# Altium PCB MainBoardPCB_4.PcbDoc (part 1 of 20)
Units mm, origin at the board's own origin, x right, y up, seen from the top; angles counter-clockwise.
Board outline 333.63 x 349.38 mm, 16 copper layers (L1, L2 (GND), L3 (Sign), L4 (GND), L5 (Sign), L6 (PWR/GND), L7(PWR/GND), L8 (Plane_GND), L9 (PWR/GND), L10 (PWR/GND), L11 (PWR/GND), L12 (Sign), L13 (GND), L14 (Sign), L15 (GND), L16), stack 2.502 mm thick; 2205 components, 1648 nets, 8314 pads, 3172 vias.
Unrouted connection lines stored in the file: 5141.
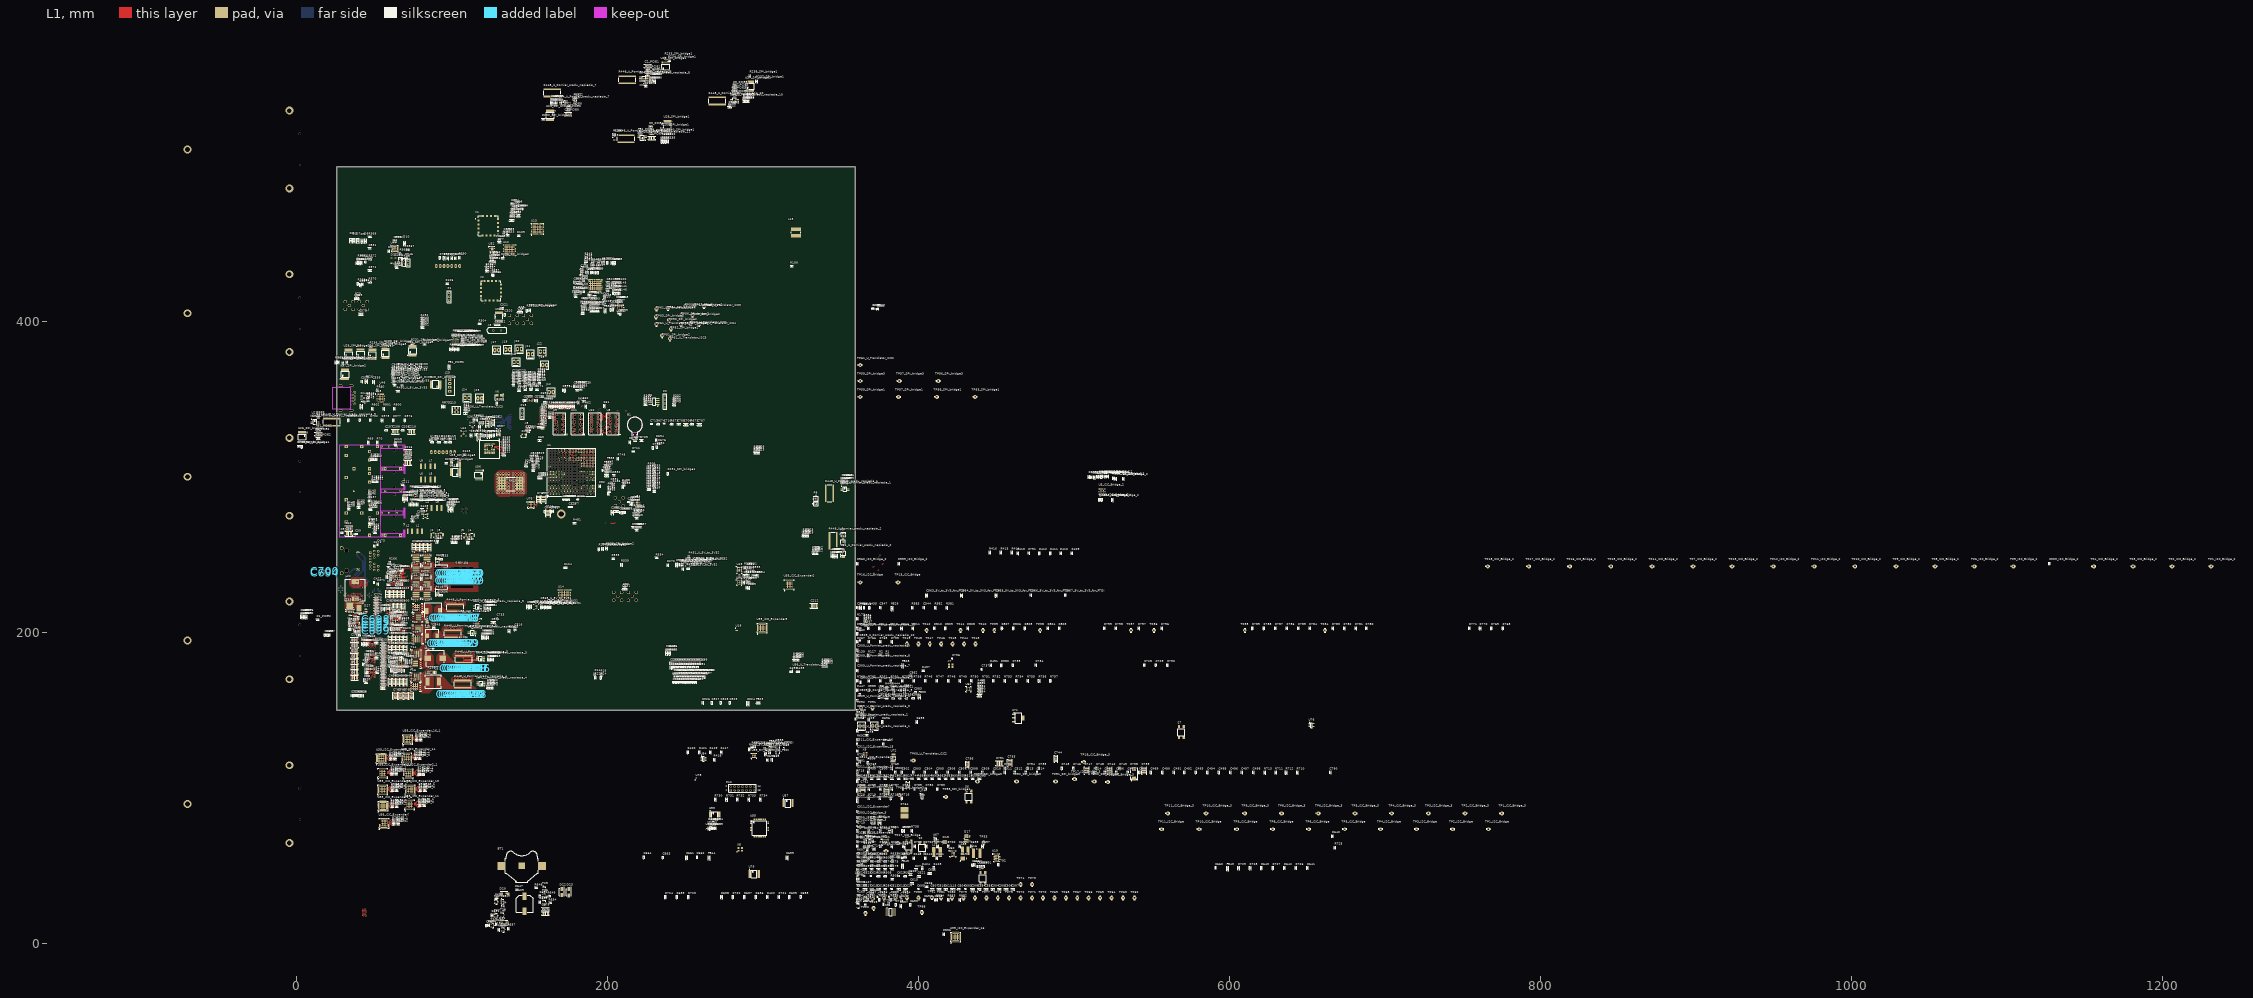
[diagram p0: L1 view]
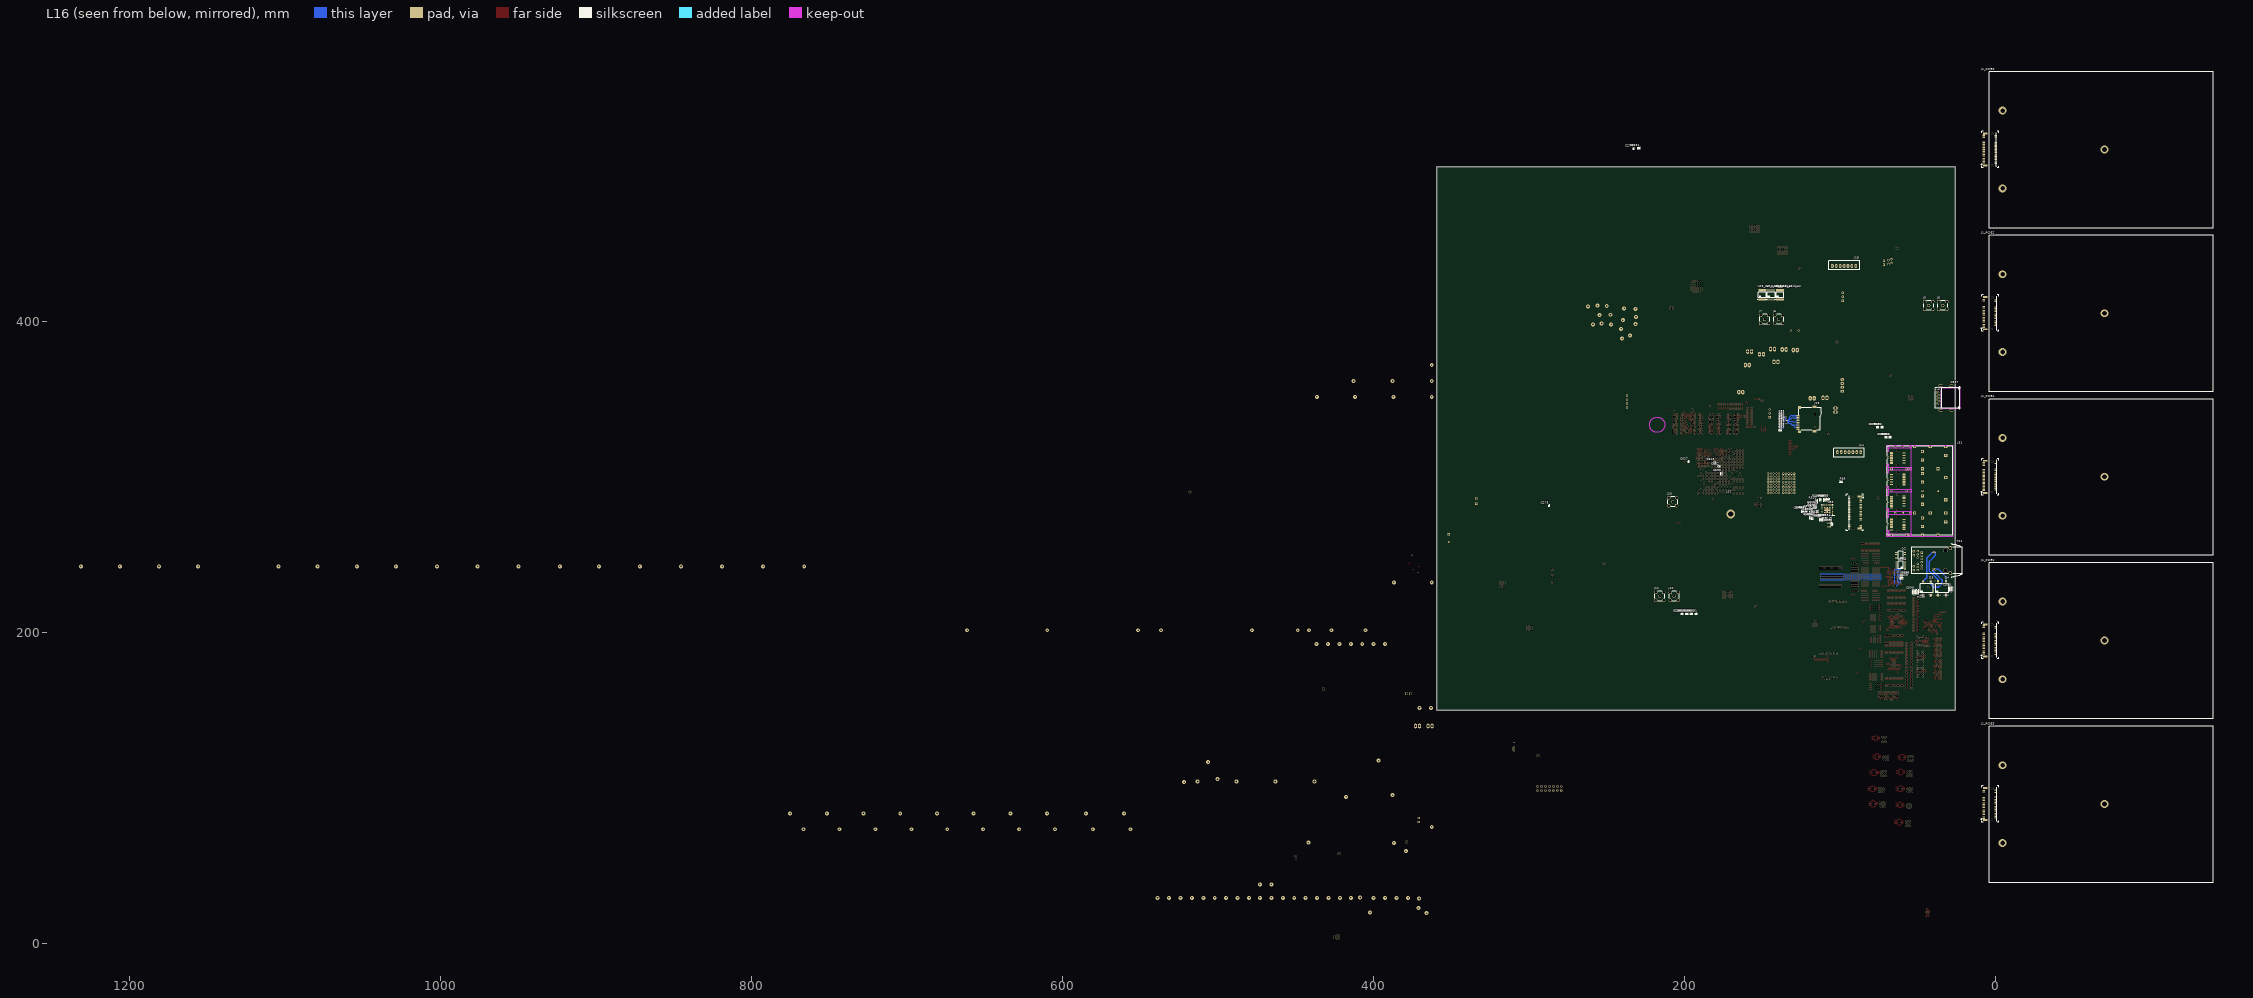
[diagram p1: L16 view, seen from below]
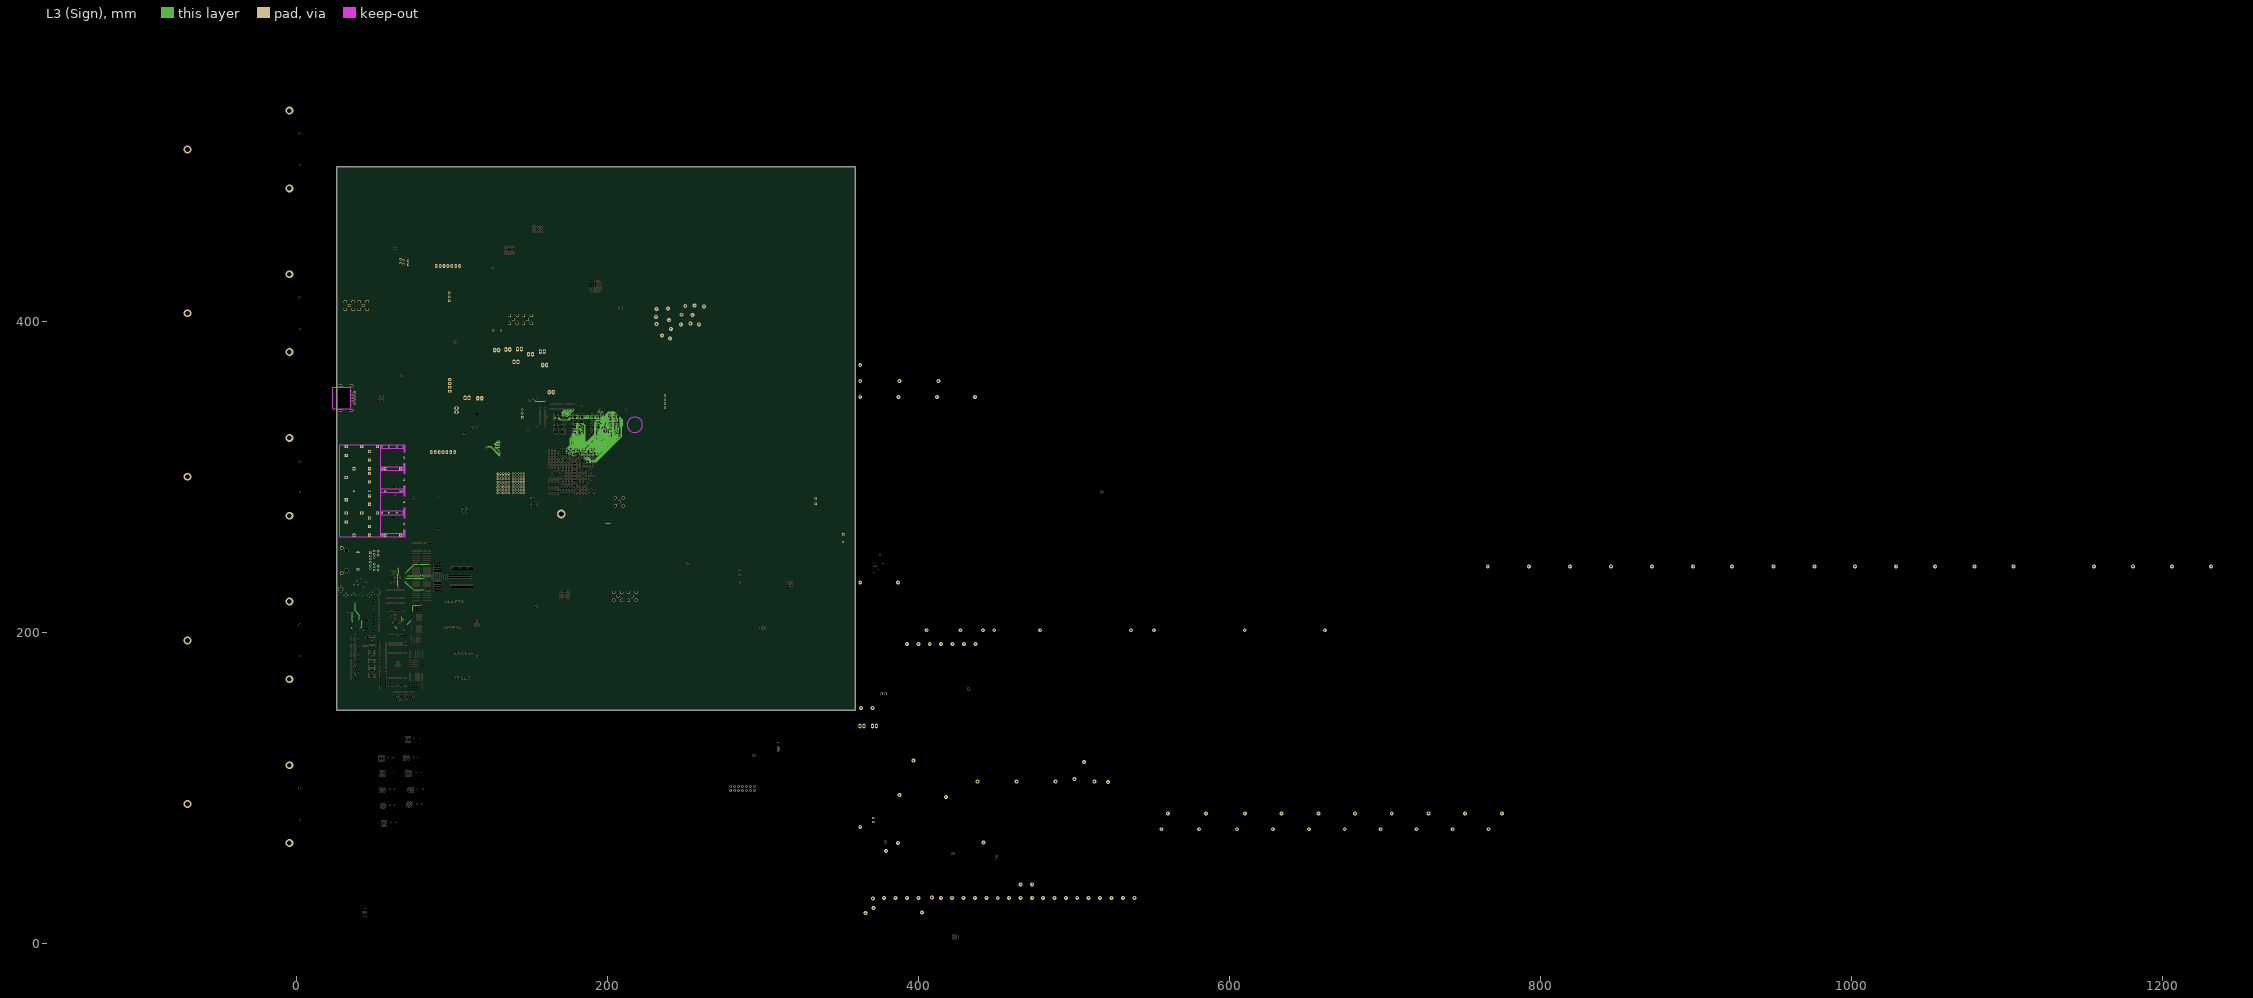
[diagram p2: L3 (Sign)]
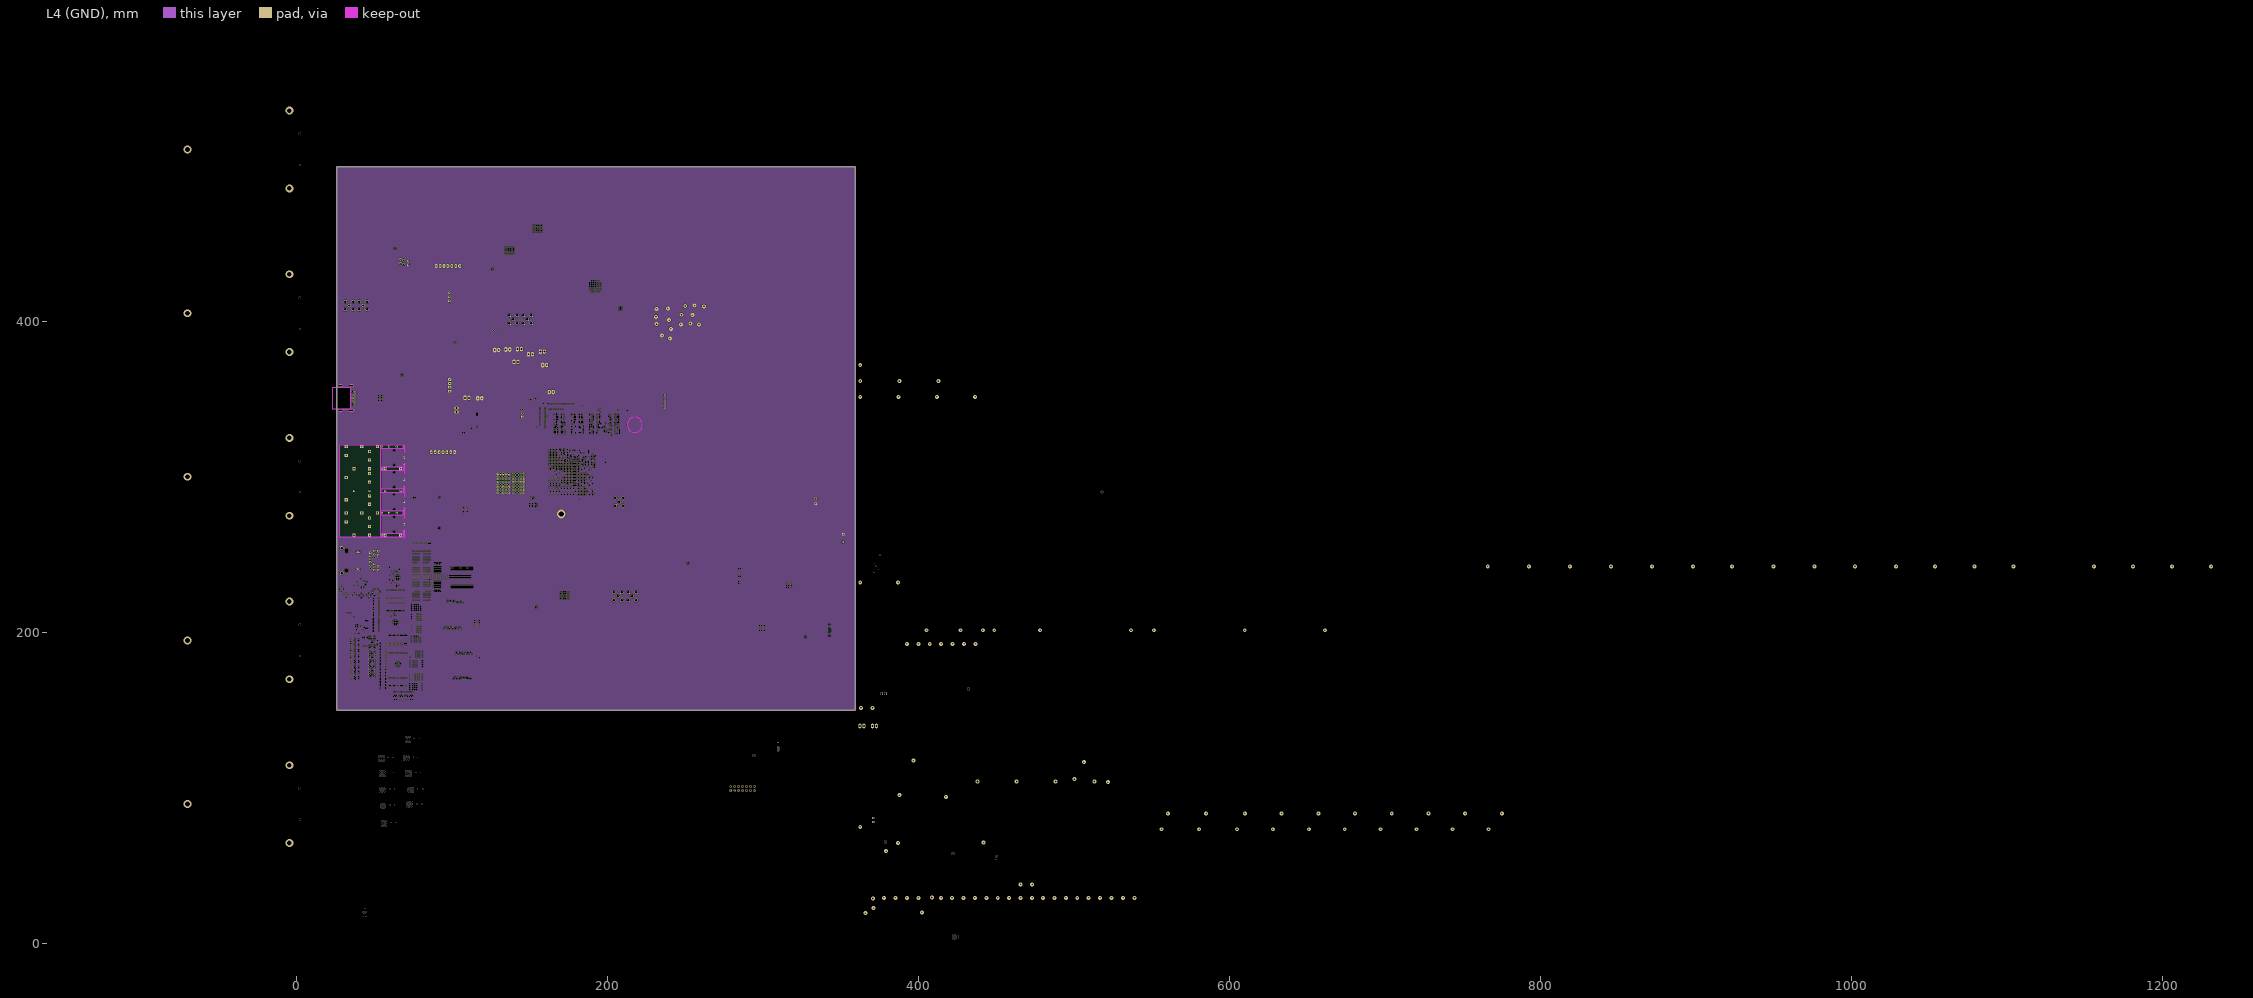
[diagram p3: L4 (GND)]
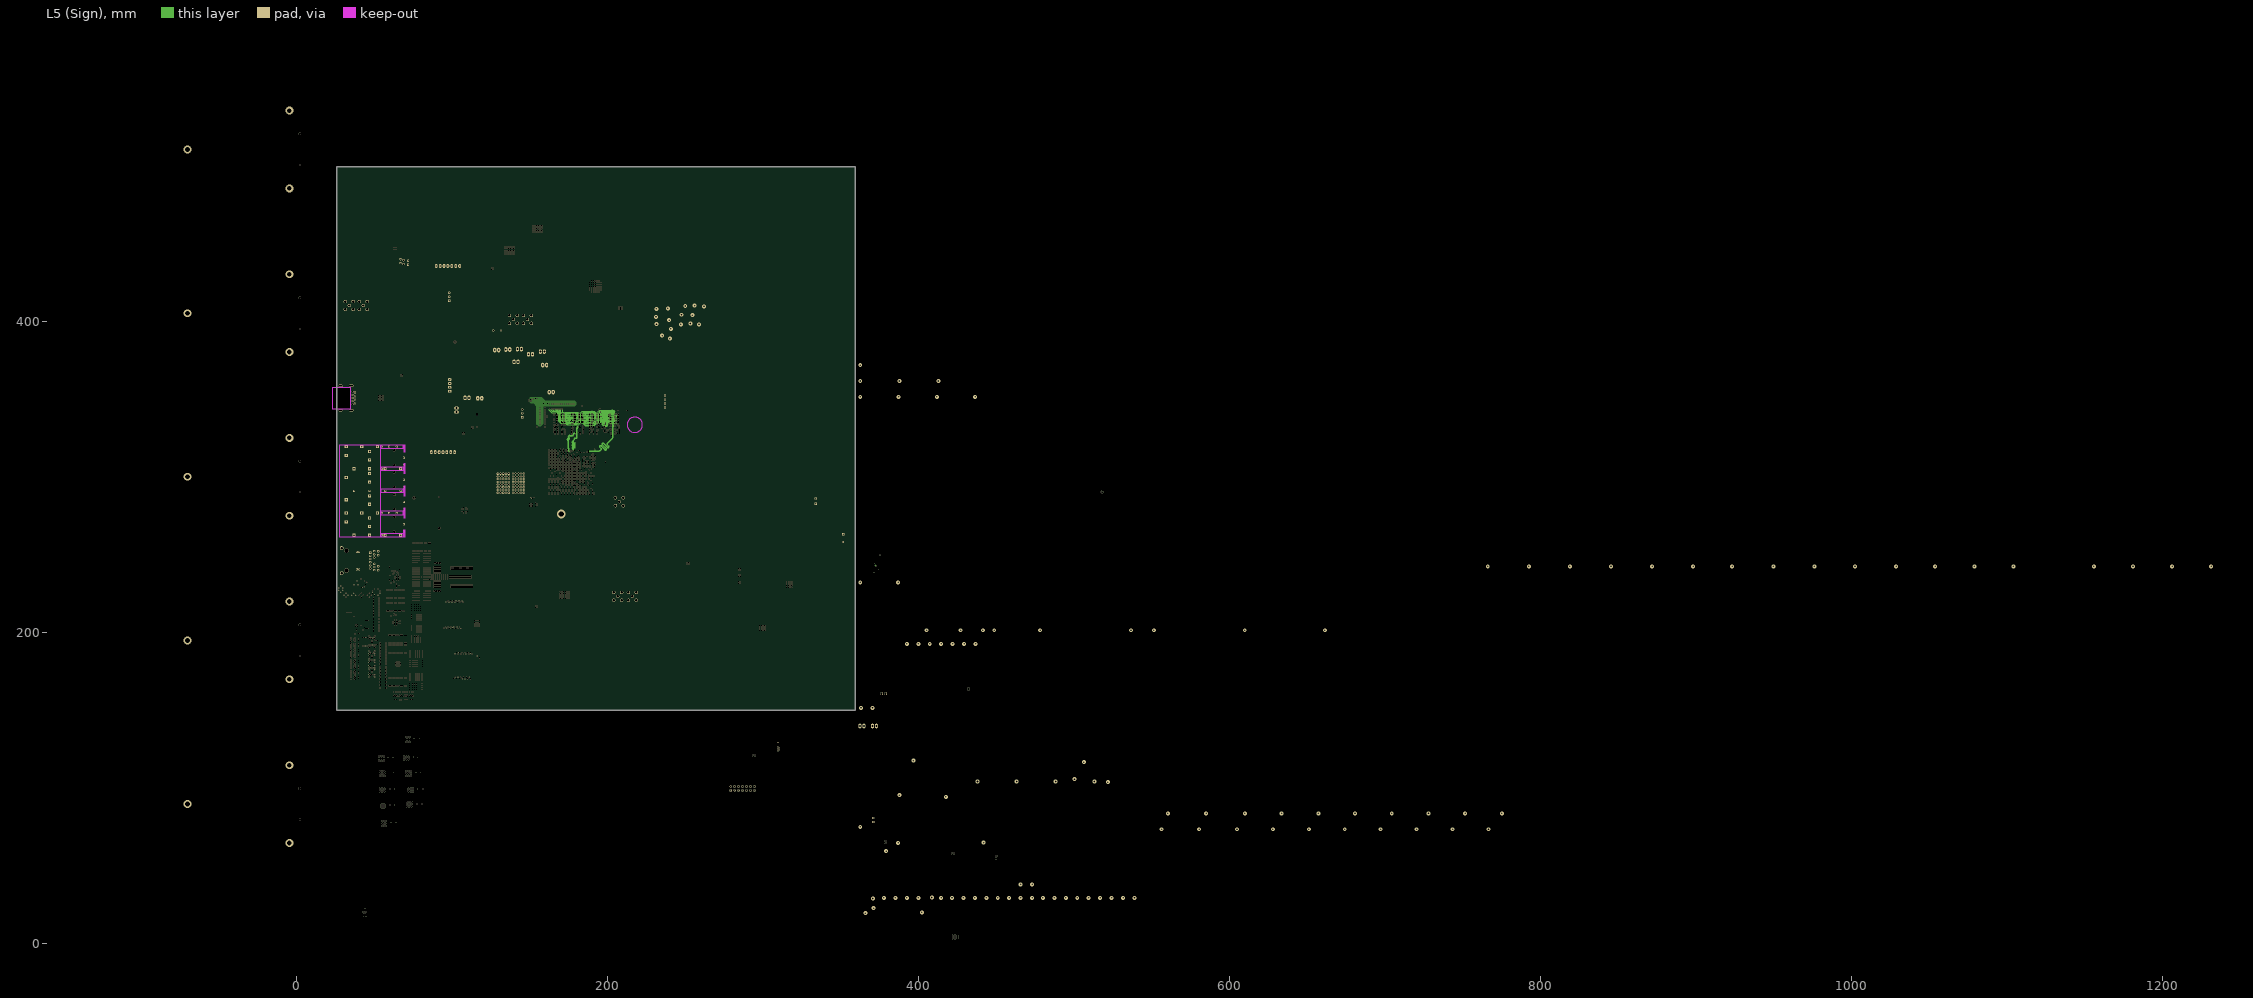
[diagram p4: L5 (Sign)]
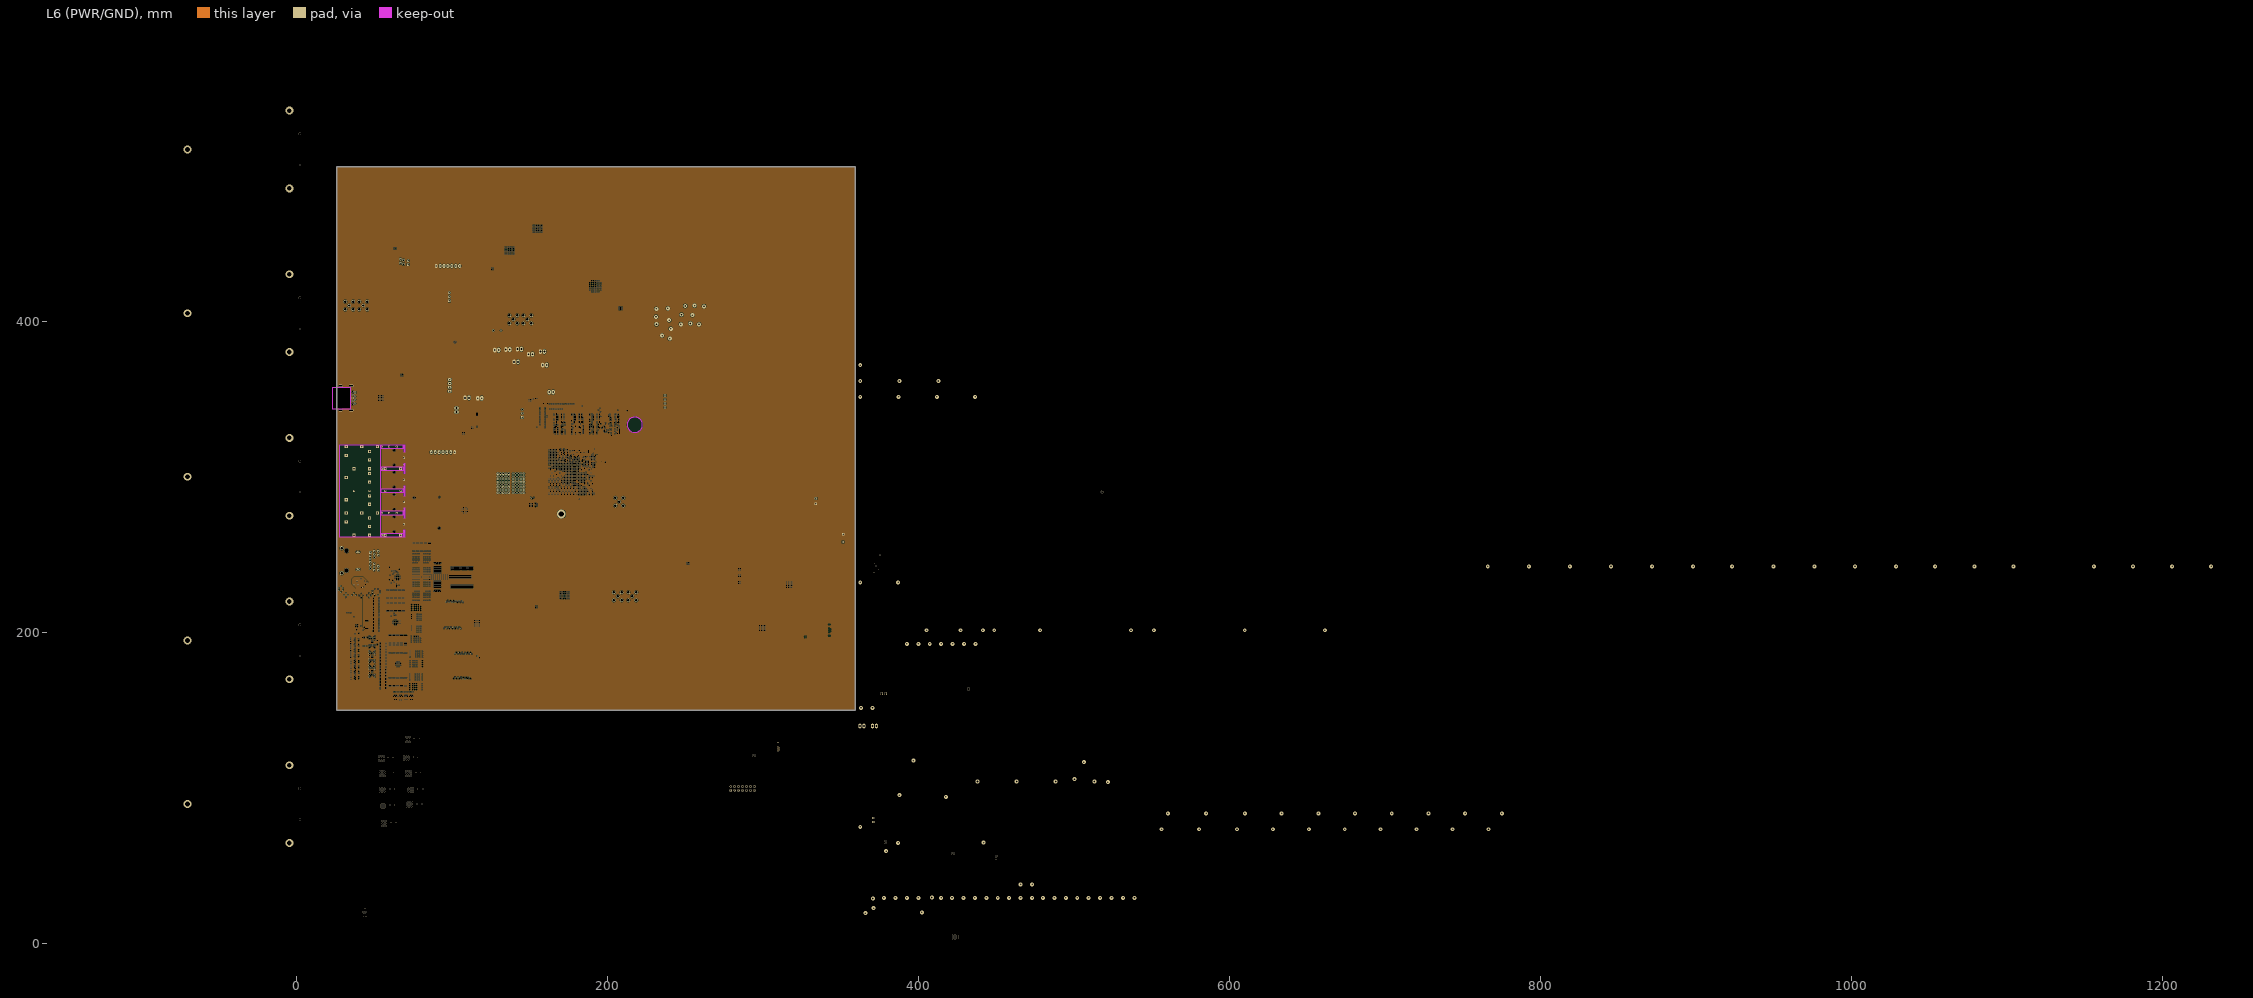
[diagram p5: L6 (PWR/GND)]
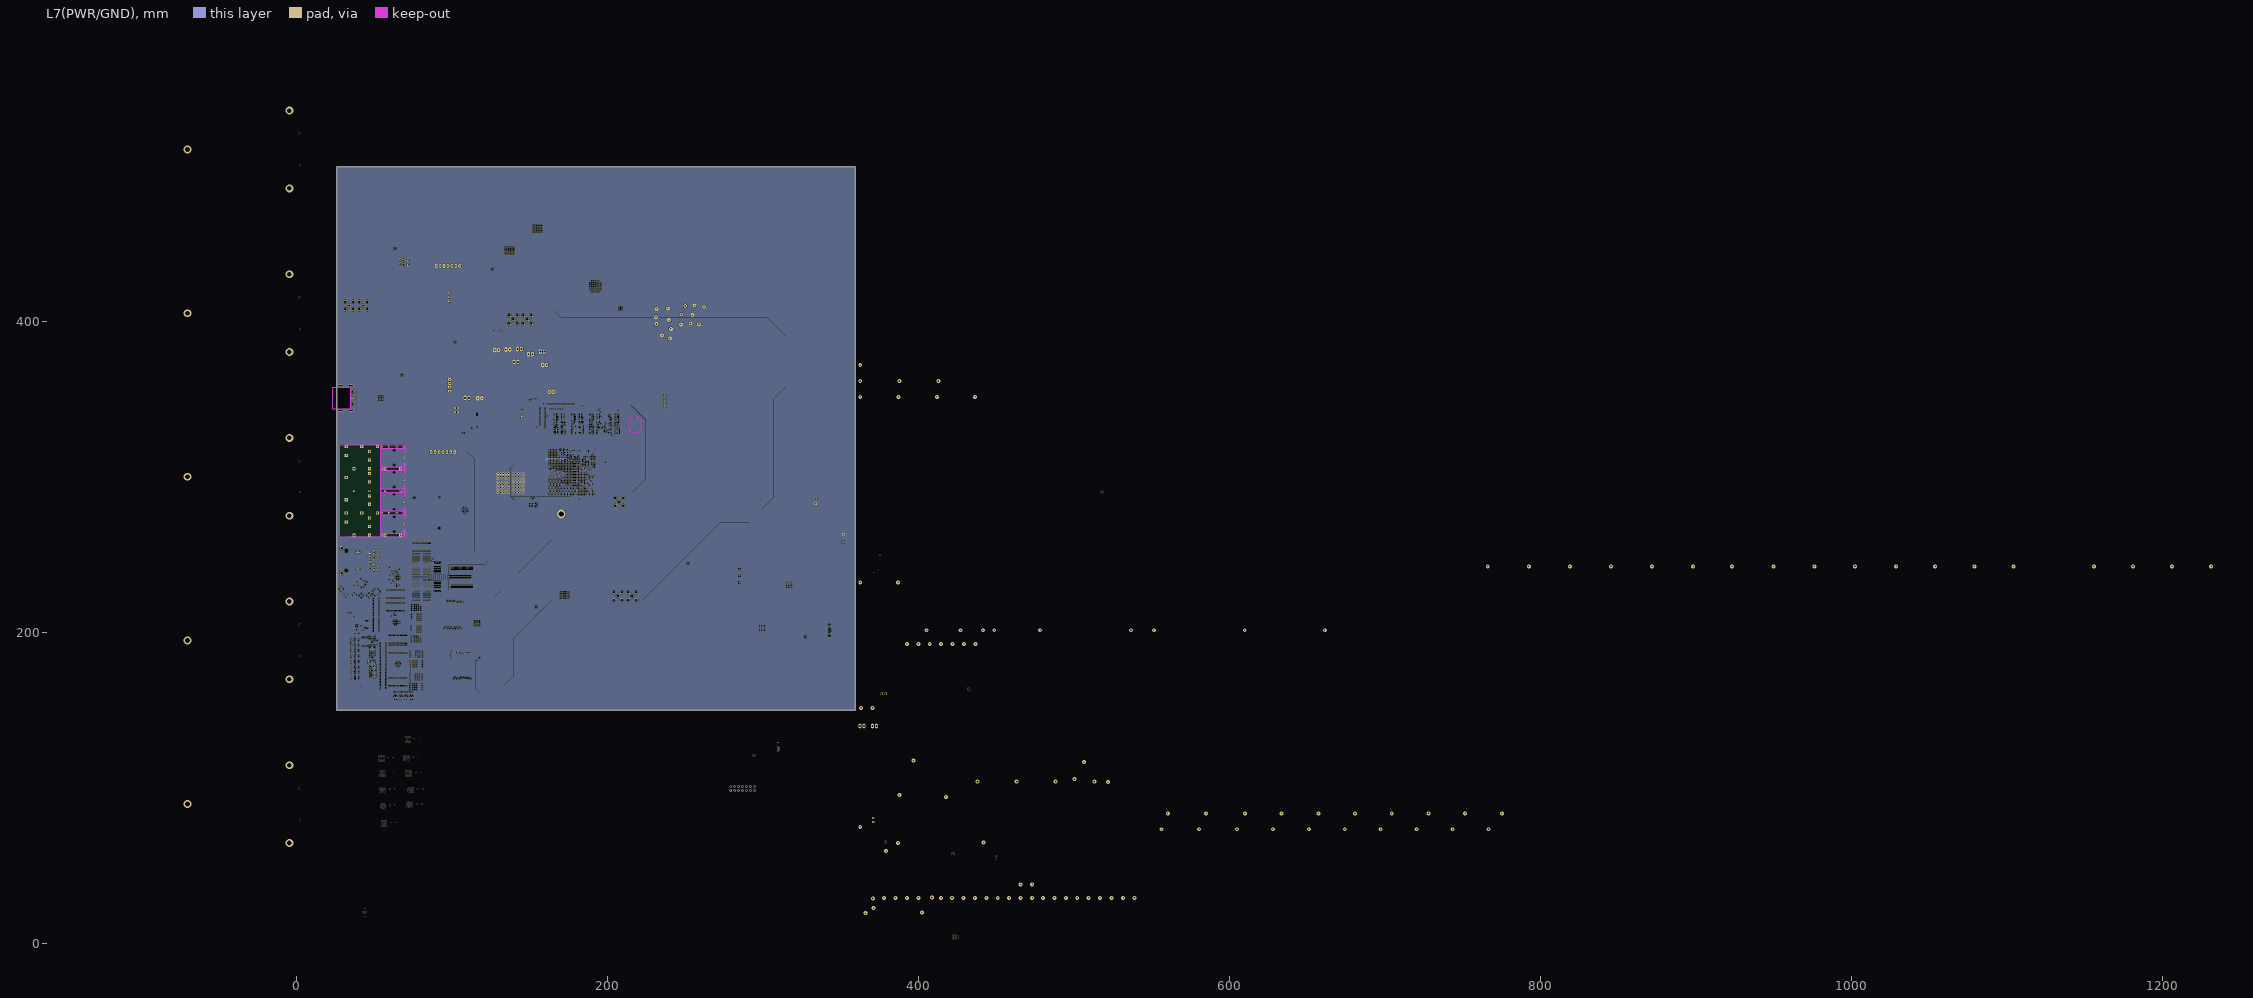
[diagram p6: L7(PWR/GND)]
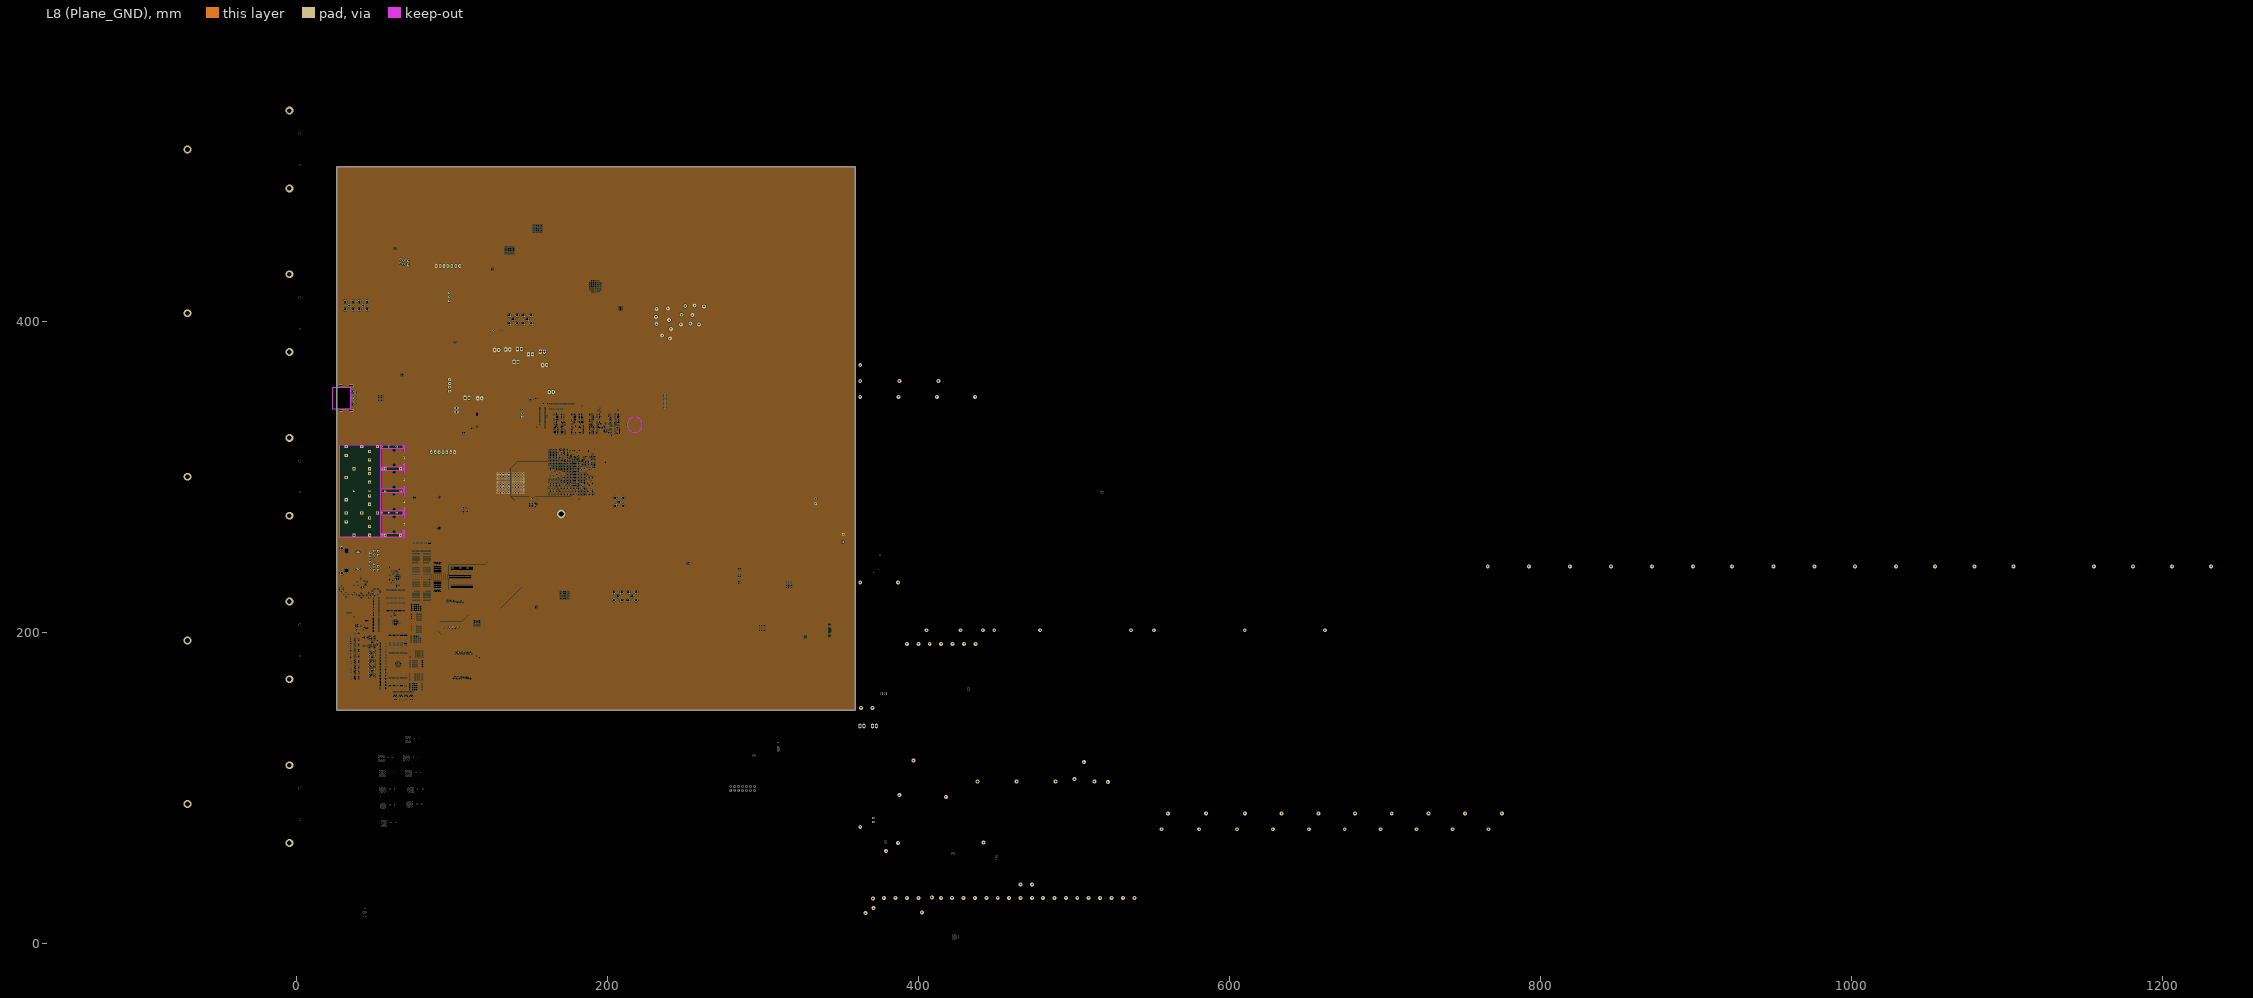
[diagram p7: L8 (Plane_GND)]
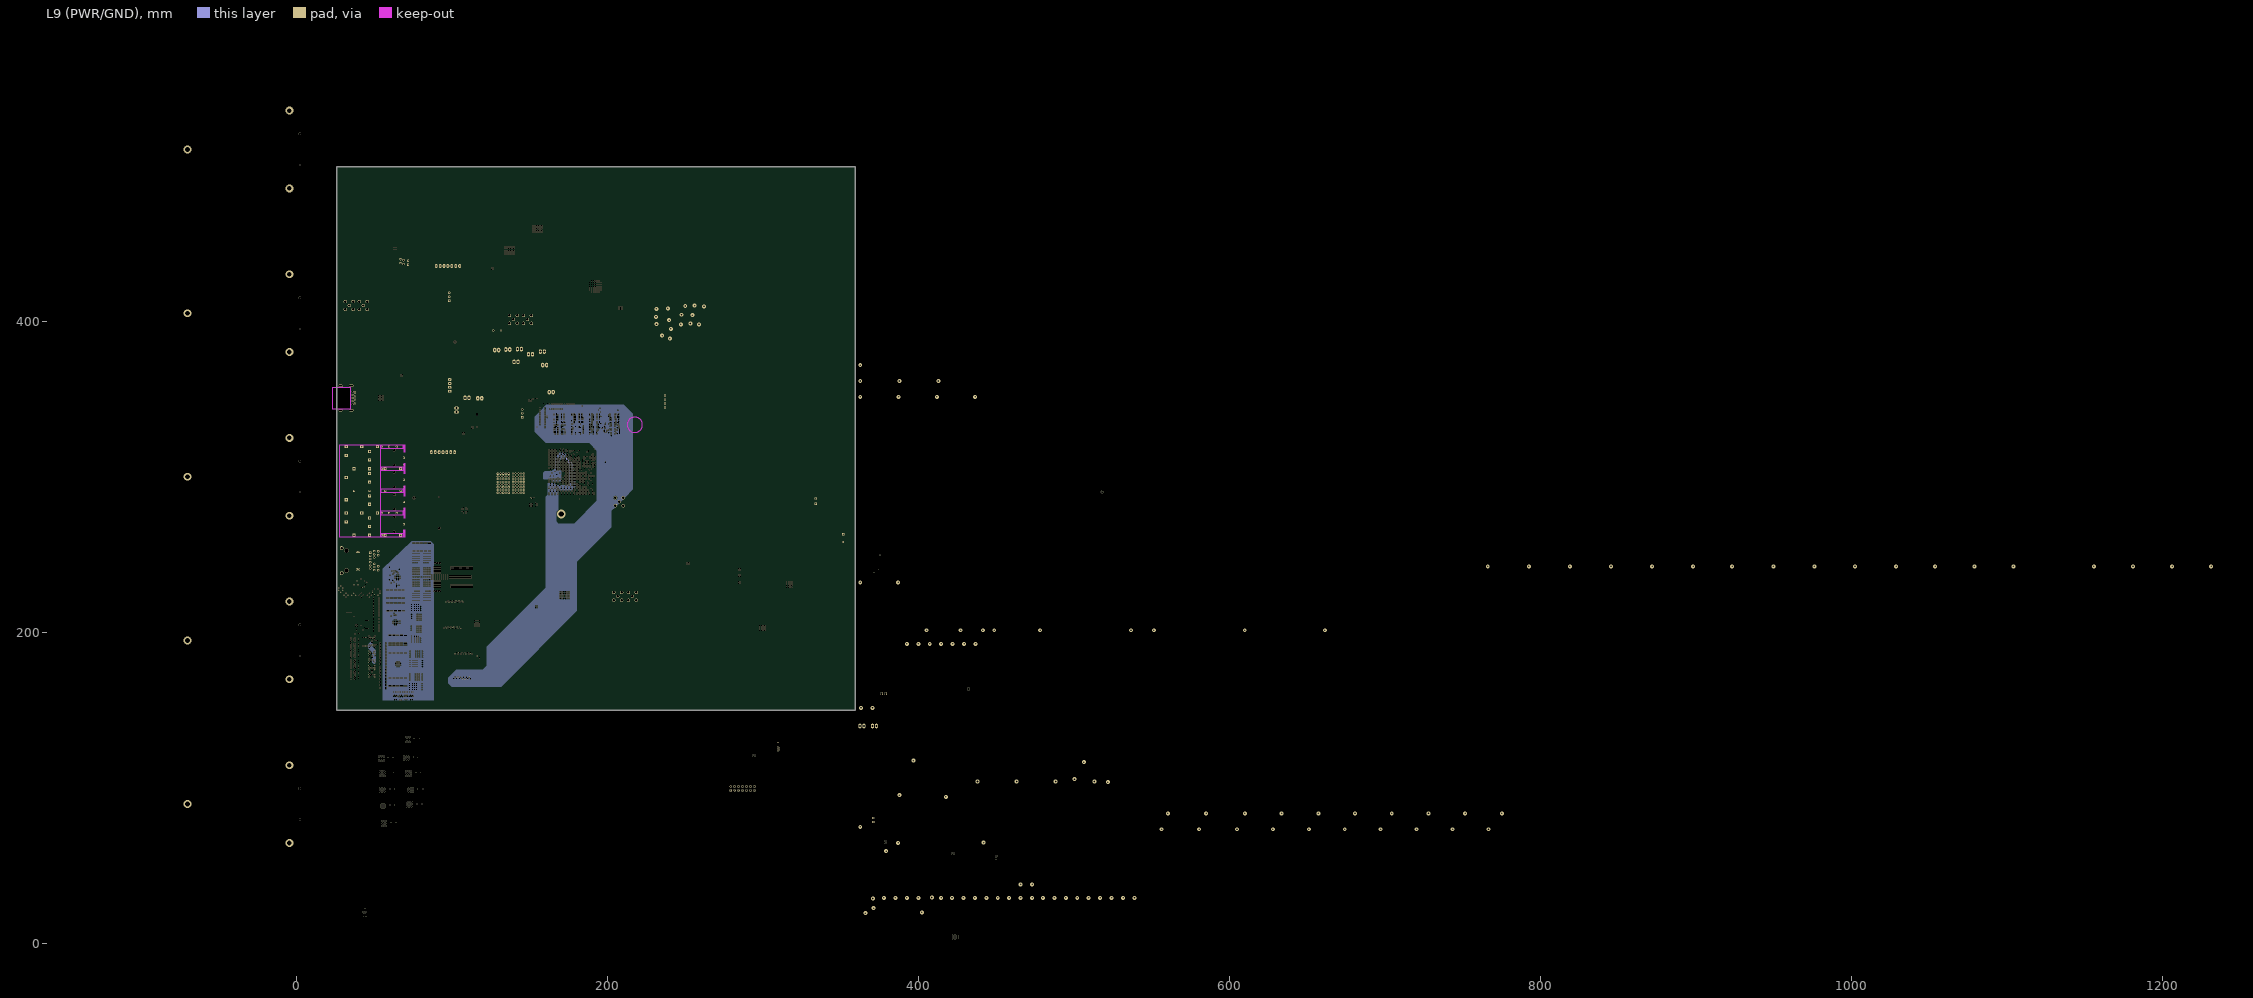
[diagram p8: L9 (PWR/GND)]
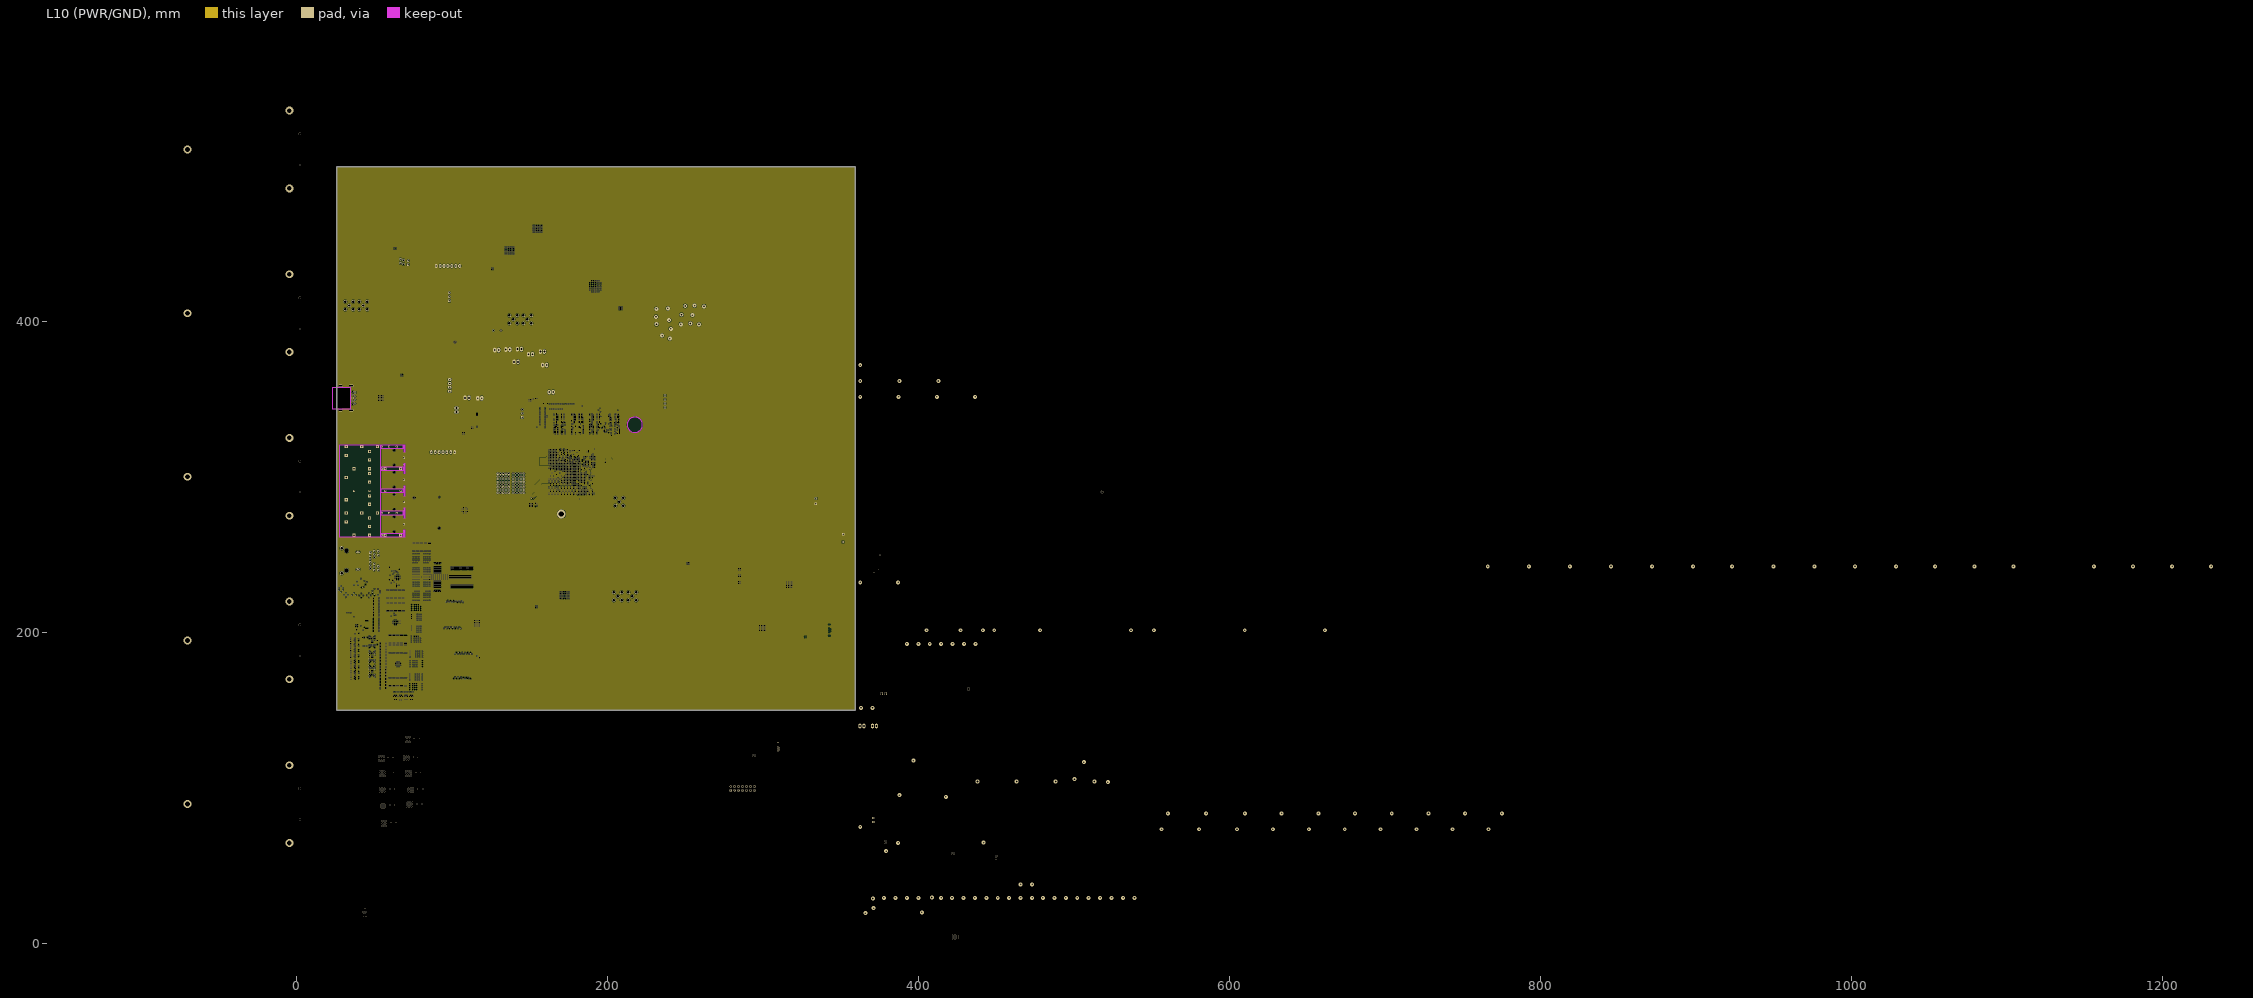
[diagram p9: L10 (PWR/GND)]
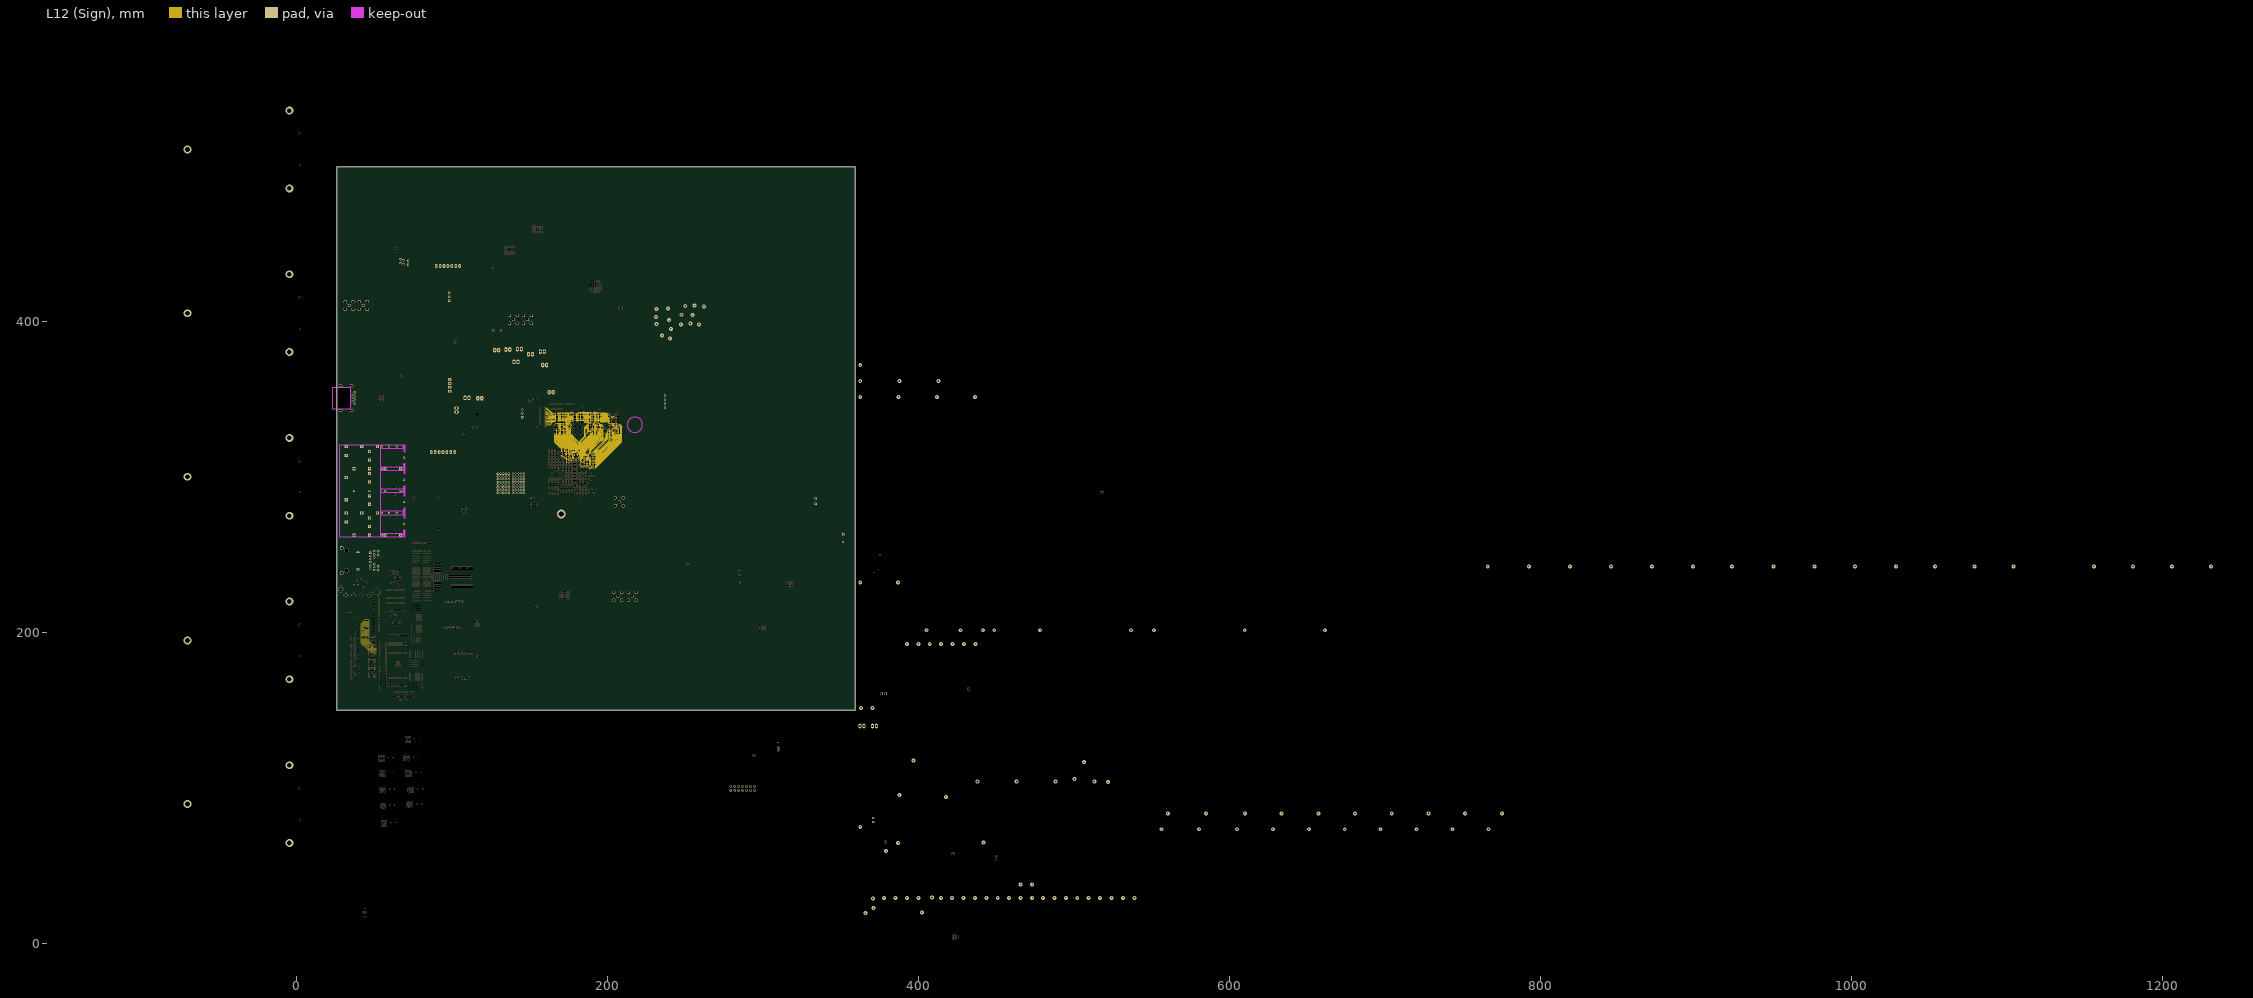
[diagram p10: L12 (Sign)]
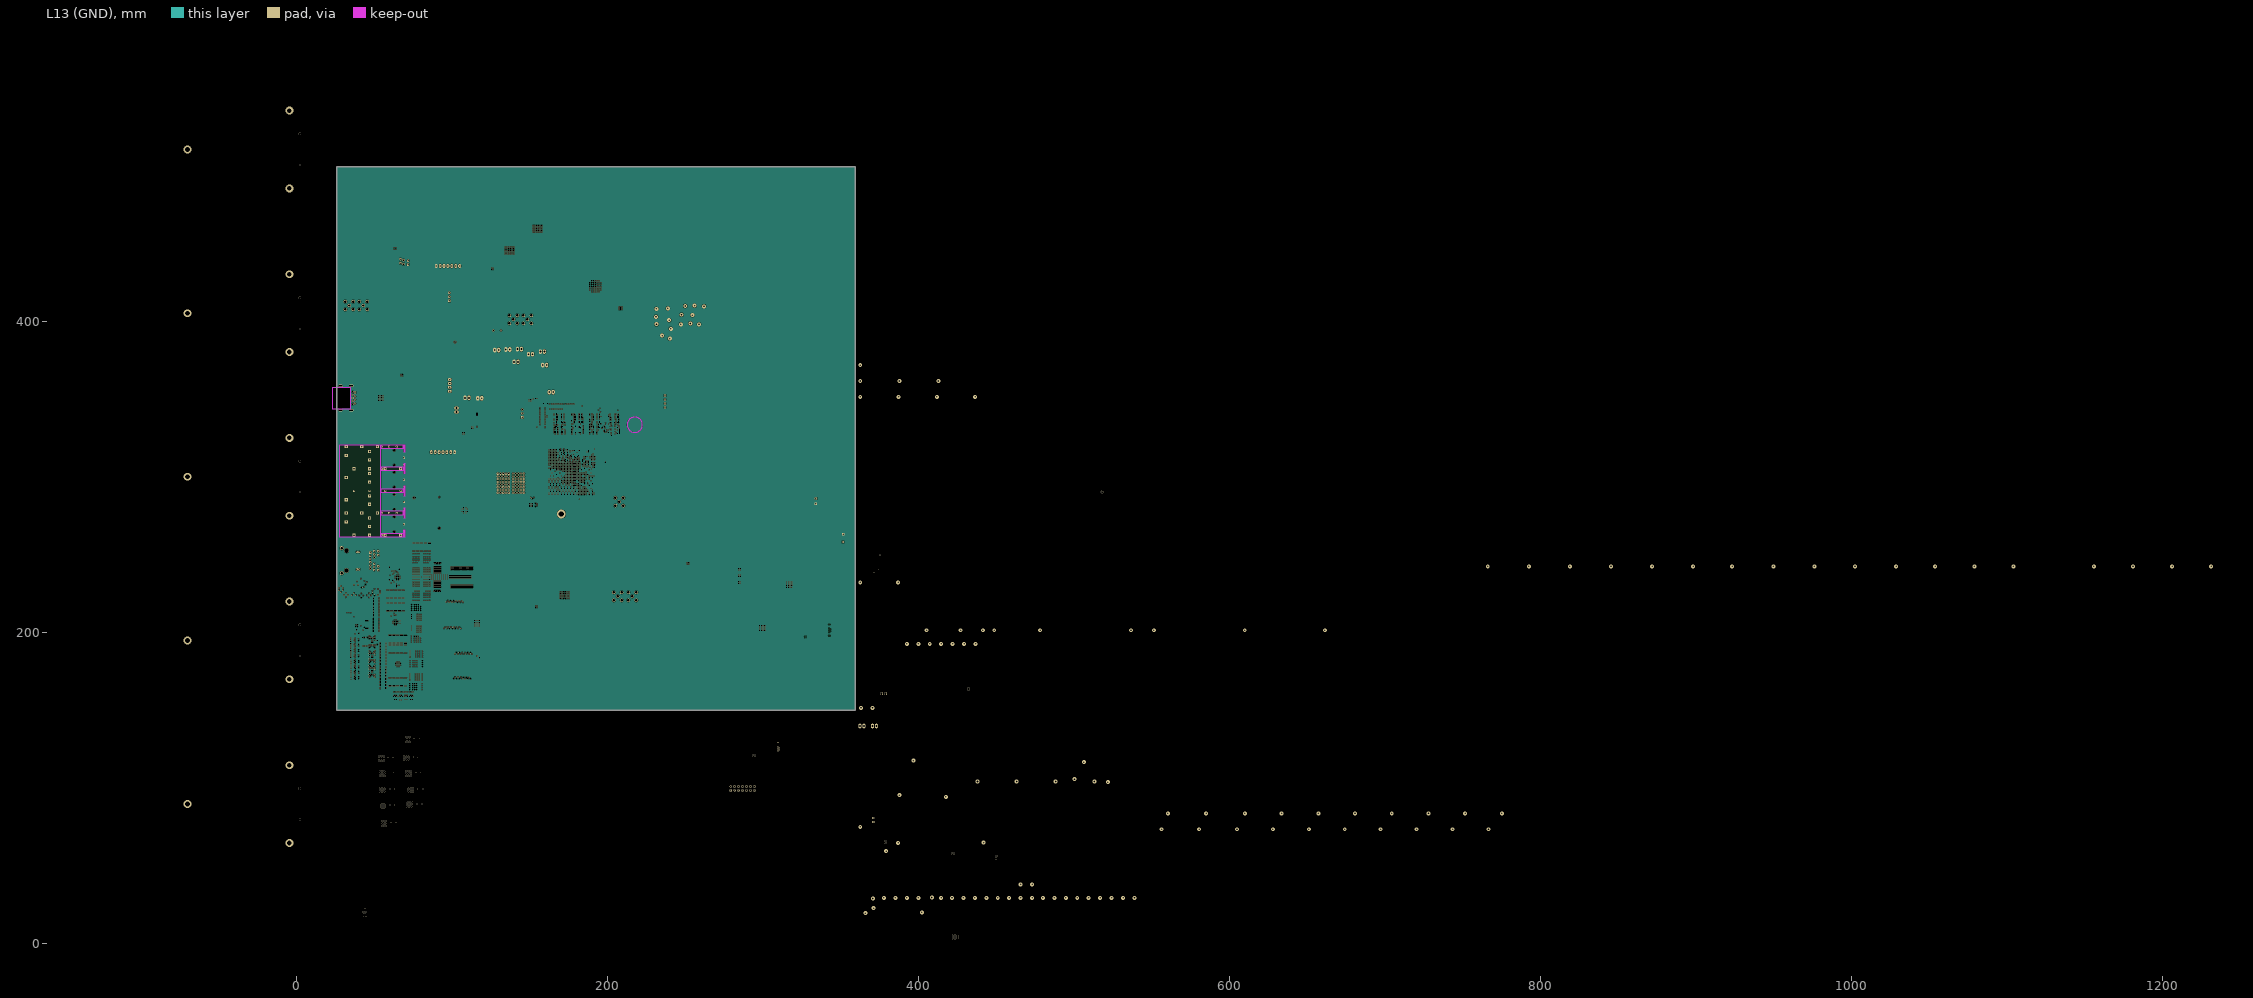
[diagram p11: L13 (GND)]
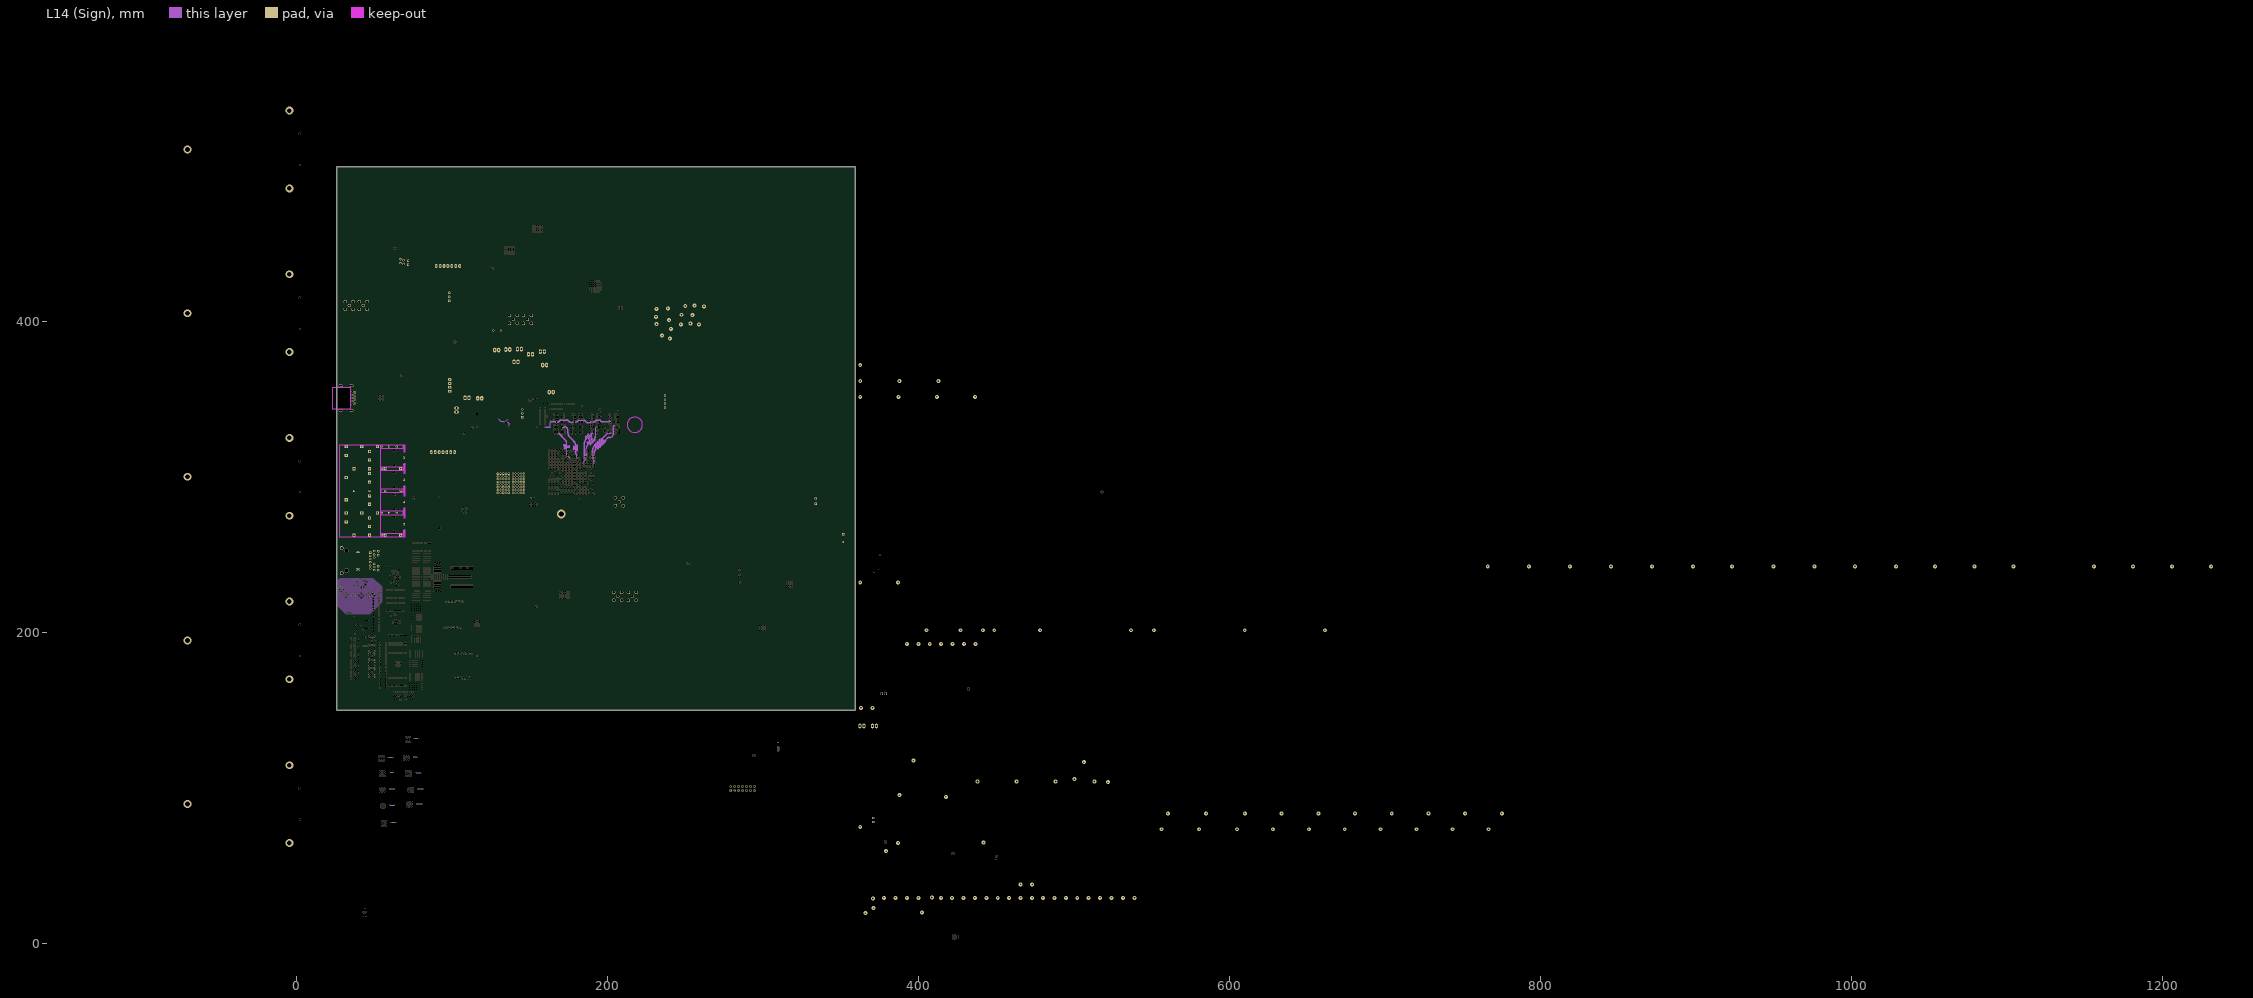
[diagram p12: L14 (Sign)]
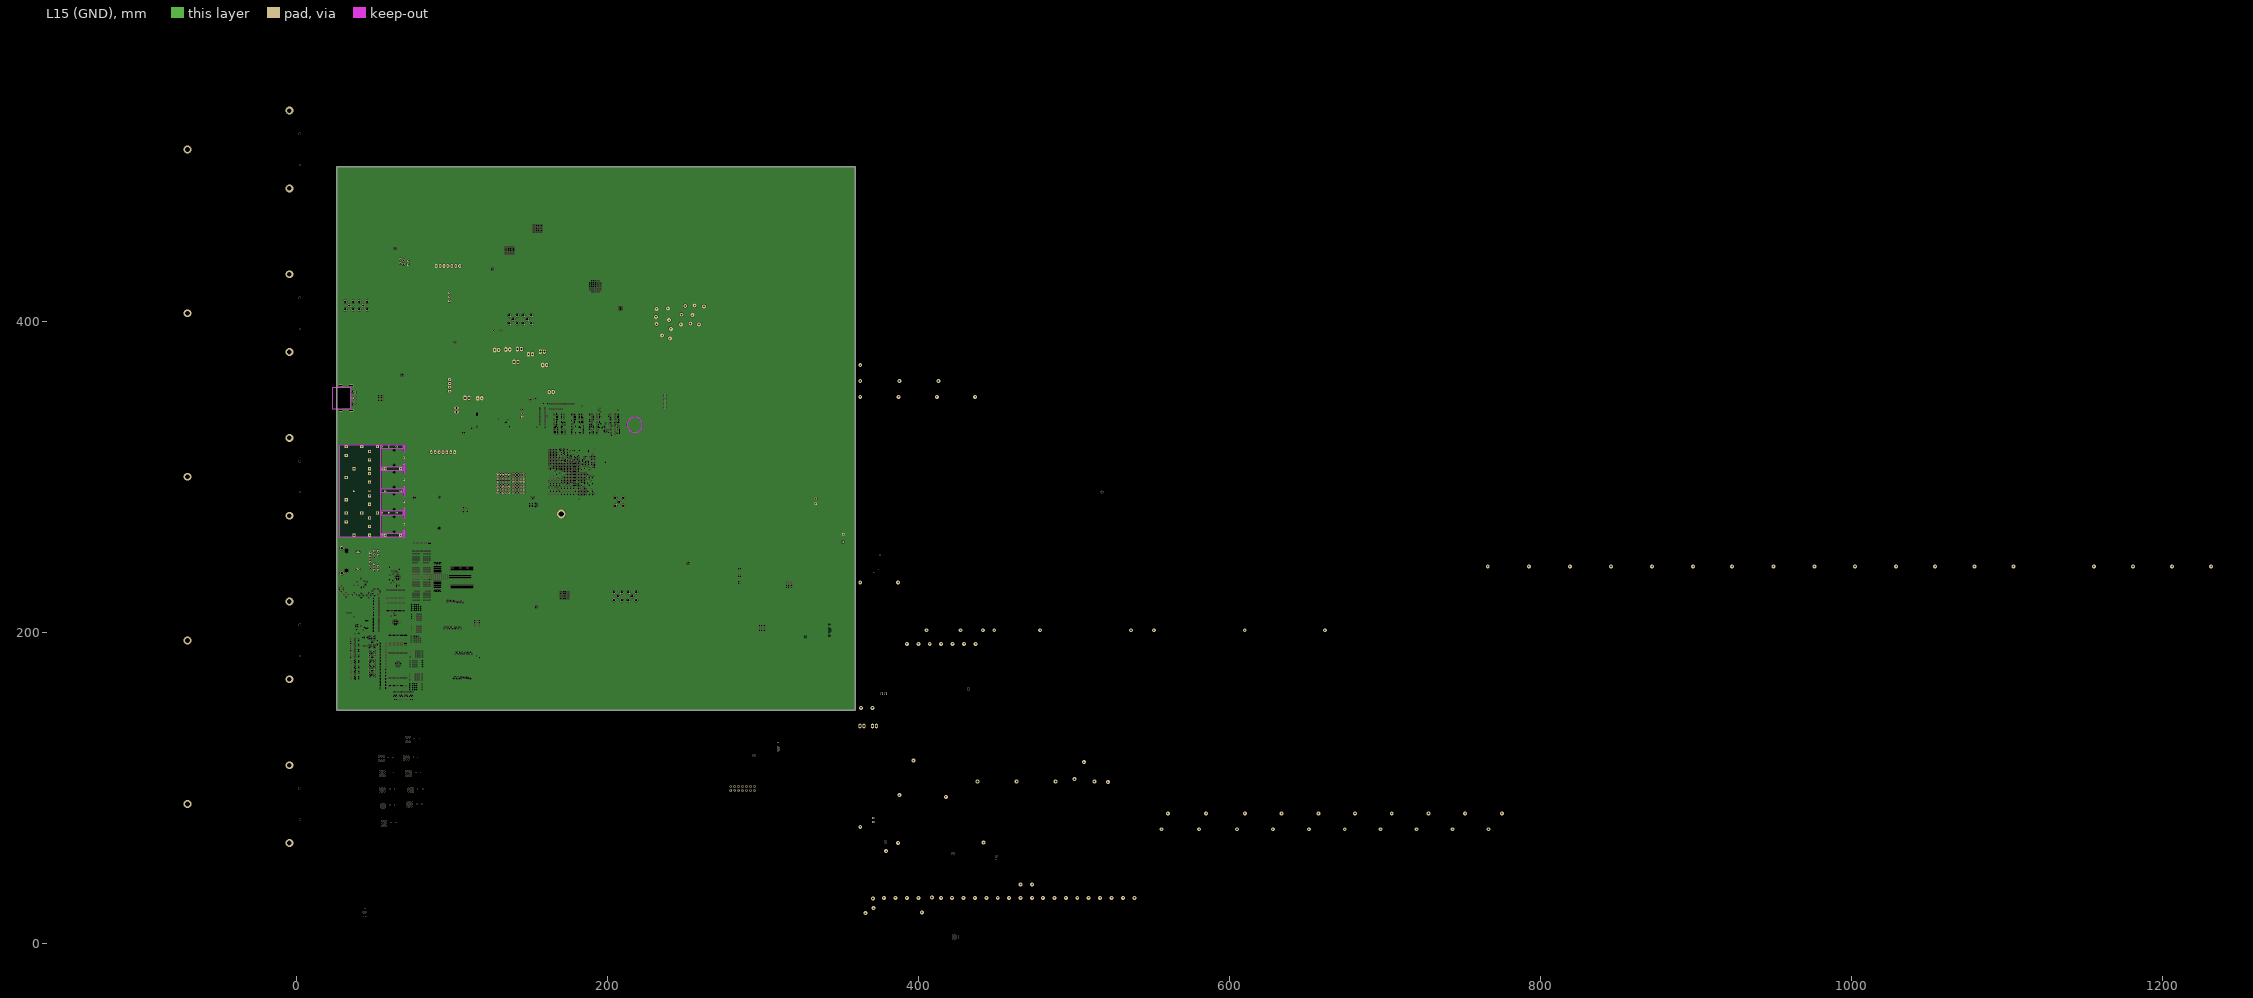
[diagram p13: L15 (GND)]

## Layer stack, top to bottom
Top Solder: solder mask 0.0254, SM-001, Dk 4
L1: signal copper 0.0635
Dielectric 1: prepreg 0.074, PP-013, Dk 4.3
L2 (GND): signal copper 0.015
Dielectric 2: core 0.114, Core-001, Dk 4.1
L3 (Sign): signal copper 0.015
Dielectric 3: prepreg 0.114, PP-013, Dk 4.3
L4 (GND): signal copper 0.015
Dielectric 4: core 0.114, Core-001, Dk 4.1
L5 (Sign): signal copper 0.015
Dielectric 5: prepreg 0.114, PP-013, Dk 4.3
L6 (PWR/GND): signal copper 0.03
Dielectric 6: core 0.203, Core-001, Dk 4.1
L7(PWR/GND): signal copper 0.03
Dielectric 7: prepreg 0.203, PP-013, Dk 4.3
L8 (Plane_GND): signal copper 0.03
Dielectric 8: core 0.203, Core-001, Dk 4.1
L9 (PWR/GND): signal copper 0.03
Dielectric 9: prepreg 0.203, PP-013, Dk 4.3
L10 (PWR/GND): signal copper 0.03
Dielectric 10: core 0.203, Core-001, Dk 4.1
L11 (PWR/GND): signal copper 0.03
Dielectric 11: prepreg 0.114, PP-013, Dk 4.3
L12 (Sign): signal copper 0.015
Dielectric 12: core 0.114, Core-001, Dk 4.1
L13 (GND): signal copper 0.015
Dielectric 13: prepreg 0.114, PP-013, Dk 4.3
L14 (Sign): signal copper 0.015
Dielectric 14: core 0.114, Core-001, Dk 4.1
L15 (GND): signal copper 0.015
Dielectric 15: prepreg 0.074, PP-013, Dk 4.3
L16: signal copper 0.0635
Bottom Solder: solder mask 0.0254, SM-001, Dk 4

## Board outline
25.87,150.012 359.499,150.012 359.499,499.389 25.87,499.389

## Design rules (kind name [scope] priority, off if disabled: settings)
BackDrilling [(InNetClass('RAM_Adress') Or InNetClass('RAM_Data_IO') Or InNetClass('RAM_Clock_Signal') Or InNetClass('RAM_DQS_Strobe'))  And IsVia] p1: maxstublength=0.381 usetopbackdrill=TRUE usebottombackdrill=TRUE holeoversize=0.025 holetolplus=0 holetolminus=0
BoardOutlineClearance [All] p1: gap=0.254 ignorepadtopadclearanceinfootprint=FALSE except(0: Arc-SplitContinuation Track-SplitContinuation SMDPad-SplitContinuation THPad-SplitContinuation Via-SplitContinuation Fill-SplitContinuation Poly-SplitContinuation Region-SplitContinuation Text-SplitContinuation)
Clearance RAM_Clearence [WithinRoom('RAM_CLK')] p1: gap=0.1 ignorepadtopadclearanceinfootprint=FALSE
Clearance "RAM_Addr to RAM_Addr" [InNetClass('Single_36_39_50_Adr') vs InNetClass('Single_36_39_50_Adr')] p2: gap=0.1 ignorepadtopadclearanceinfootprint=FALSE
Clearance "RAM_Addr to RAM_PWR" [InNetClass('Single_36_39_50_Adr') vs InNet('RAM_Vcc1V2')] p3: gap=0.1 ignorepadtopadclearanceinfootprint=FALSE
Clearance "RAM_Addr to other" [InNetClass('Single_36_39_50_Adr')] p4: gap=0.15 ignorepadtopadclearanceinfootprint=TRUE
Clearance [All] p5: gap=0.1 ignorepadtopadclearanceinfootprint=FALSE
DiffPairsRouting RAM_Diff86 [InDifferentialPairClass('Diff_76_to_90_Ram_CLK') and (WithinRoom('RAM_1')or WithinRoom('RAM_2')or WithinRoom('RAM_3')or WithinRoom('Ram_4')or WithinRoom('FPGA_Room'))and  OnTopLayer] p1: maxlimit=0.254 minlimit=0.148 mostfreqgap=0.254 toplayer_mingap=0.2 toplayer_maxgap=0.22 toplayer_prefgap=0.21 toplayer_minwidth=0.1 toplayer_maxwidth=0.12 toplayer_prefwidth=0.1 midlayer2_maxgap=0.15 midlayer2_prefgap=0.149 midlayer2_minwidth=0.1 midlayer2_maxwidth=0.12 midlayer2_prefwidth=0.1 midlayer5_maxgap=0.15 midlayer5_prefgap=0.149 midlayer5_minwidth=0.1 midlayer5_maxwidth=0.12 midlayer5_prefwidth=0.1 midlayer8_maxgap=0.15 midlayer8_prefgap=0.149 midlayer8_minwidth=0.1 midlayer8_maxwidth=0.12 midlayer8_prefwidth=0.1 midlayer13_maxgap=0.15 midlayer13_prefgap=0.149 midlayer13_minwidth=0.1 midlayer13_maxwidth=0.12 midlayer13_prefwidth=0.1 bottomlayer_mingap=0.2 bottomlayer_maxgap=0.22 bottomlayer_prefgap=0.21 bottomlayer_minwidth=0.1 bottomlayer_maxwidth=0.12 bottomlayer_prefwidth=0.1 impedanceprofiledriven=TRUE impedanceprofileid={1AFD27EA-460E-472B-BC44-4C5C59E93A8B} maxuncoupledlength=12.7 // breakout
DiffPairsRouting RAM_Diff90 [InDifferentialPairClass('Diff_76_to_90_Ram_CLK') and (WithinRoom('RAM_1')or WithinRoom('RAM_2')or WithinRoom('RAM_3')or WithinRoom('Ram_4')or WithinRoom('FPGA_Room')or WithinRoom('RAM_CLK'))and (not OnTopLayer)] p2: maxlimit=0.31 minlimit=0.127 mostfreqgap=0.254 toplayer_prefgap=0.31 toplayer_minwidth=0.018 toplayer_maxwidth=0.112 toplayer_prefwidth=0.1 midlayer2_maxgap=0.262 midlayer2_prefgap=0.262 midlayer2_minwidth=0.011 midlayer2_maxwidth=0.1 midlayer2_prefwidth=0.1 midlayer5_maxgap=0.262 midlayer5_prefgap=0.262 midlayer5_minwidth=0.011 midlayer5_maxwidth=0.1 midlayer5_prefwidth=0.1 midlayer8_maxgap=0.262 midlayer8_prefgap=0.262 midlayer8_minwidth=0.011 midlayer8_maxwidth=0.1 midlayer8_prefwidth=0.1 midlayer13_maxgap=0.262 midlayer13_prefgap=0.262 midlayer13_minwidth=0.011 midlayer13_maxwidth=0.1 midlayer13_prefwidth=0.1 bottomlayer_prefgap=0.31 bottomlayer_minwidth=0.018 bottomlayer_maxwidth=0.112 bottomlayer_prefwidth=0.1 impedanceprofiledriven=TRUE impedanceprofileid={1D82871A-FACB-482B-B08F-C93C2922060F} maxuncoupledlength=12.7
DiffPairsRouting Diff_76 [InDifferentialPairClass('Diff_76_to_90_Ram_CLK')] p3: maxlimit=0.254 minlimit=0.074 mostfreqgap=0.254 toplayer_mingap=0.115 toplayer_maxgap=0.154 toplayer_prefgap=0.115 toplayer_minwidth=0.1 toplayer_maxwidth=0.159 toplayer_prefwidth=0.1 midlayer2_maxgap=0.127 midlayer2_prefgap=0.074 midlayer2_minwidth=0.1 midlayer2_maxwidth=0.137 midlayer2_prefwidth=0.1 midlayer5_maxgap=0.127 midlayer5_prefgap=0.074 midlayer5_minwidth=0.1 midlayer5_maxwidth=0.137 midlayer5_prefwidth=0.1 midlayer8_maxgap=0.127 midlayer8_prefgap=0.074 midlayer8_minwidth=0.1 midlayer8_maxwidth=0.137 midlayer8_prefwidth=0.1 midlayer13_maxgap=0.127 midlayer13_prefgap=0.074 midlayer13_minwidth=0.1 midlayer13_maxwidth=0.137 midlayer13_prefwidth=0.1 bottomlayer_mingap=0.115 bottomlayer_maxgap=0.154 bottomlayer_prefgap=0.115 bottomlayer_minwidth=0.1 bottomlayer_maxwidth=0.159 bottomlayer_prefwidth=0.1 impedanceprofiledriven=TRUE impedanceprofileid={BD08387B-4D6E-4BB2-82BF-460CD7A1F64F} maxuncoupledlength=12.7
DiffPairsRouting RAM_DQS [InDifferentialPairClass('Diff_76_to_90_Ram_DQS')] p4: maxlimit=0.254 minlimit=0.127 mostfreqgap=0.254 toplayer_maxgap=0.127 toplayer_prefgap=0.127 toplayer_minwidth=0.123 toplayer_maxwidth=0.159 toplayer_prefwidth=0.124 midlayer1_maxgap=0.127 midlayer1_prefgap=0.127 midlayer1_minwidth=0.105 midlayer1_maxwidth=0.105 midlayer1_prefwidth=0.105 midlayer2_maxgap=0.127 midlayer2_prefgap=0.127 midlayer2_minwidth=0.105 midlayer2_maxwidth=0.137 midlayer2_prefwidth=0.105 midlayer3_mingap=0.254 midlayer3_minwidth=0.381 midlayer3_maxwidth=0.381 midlayer3_prefwidth=0.381 midlayer4_mingap=0.254 midlayer4_minwidth=0.381 midlayer4_maxwidth=0.381 midlayer4_prefwidth=0.381 midlayer5_maxgap=0.127 midlayer5_prefgap=0.127 midlayer5_minwidth=0.105 midlayer5_maxwidth=0.127 midlayer5_prefwidth=0.105 midlayer6_maxgap=0.127 midlayer6_prefgap=0.127 midlayer6_minwidth=0.105 midlayer6_maxwidth=0.105 midlayer6_prefwidth=0.105 midlayer7_maxgap=0.127 midlayer7_prefgap=0.127 midlayer7_minwidth=0.084 midlayer7_maxwidth=0.084 midlayer7_prefwidth=0.084 midlayer8_maxgap=0.127 midlayer8_prefgap=0.127 midlayer8_minwidth=0.105 midlayer8_maxwidth=0.137 midlayer8_prefwidth=0.105 midlayer9_mingap=0.254 midlayer9_minwidth=0.381 midlayer9_maxwidth=0.381 midlayer9_prefwidth=0.381 midlayer10_mingap=0.254 midlayer10_minwidth=0.381 midlayer10_maxwidth=0.381 midlayer10_prefwidth=0.381 midlayer11_mingap=0.254 midlayer11_minwidth=0.381 midlayer11_maxwidth=0.381 midlayer11_prefwidth=0.381 midlayer12_mingap=0.254 midlayer12_minwidth=0.381 midlayer12_maxwidth=0.381 midlayer12_prefwidth=0.381 midlayer13_maxgap=0.127 midlayer13_prefgap=0.127 midlayer13_minwidth=0.105 midlayer13_maxwidth=0.137 midlayer13_prefwidth=0.105 midlayer14_maxgap=0.127 midlayer14_prefgap=0.127 midlayer14_minwidth=0.084 midlayer14_maxwidth=0.102 midlayer14_prefwidth=0.084 bottomlayer_maxgap=0.127 bottomlayer_prefgap=0.127 bottomlayer_minwidth=0.123 bottomlayer_maxwidth=0.159 bottomlayer_prefwidth=0.124 maxuncoupledlength=12.7
DiffPairsRouting RAM_Diff_76_86_90_Addr [InDifferentialPairClass('Diff_76_to_90_Ram_CLK')] p5 off: maxlimit=0.254 minlimit=0.148 mostfreqgap=0.254 toplayer_mingap=0.2 toplayer_maxgap=0.22 toplayer_prefgap=0.21 toplayer_minwidth=0.1 toplayer_maxwidth=0.12 toplayer_prefwidth=0.1 midlayer2_maxgap=0.15 midlayer2_prefgap=0.149 midlayer2_minwidth=0.1 midlayer2_maxwidth=0.12 midlayer2_prefwidth=0.1 midlayer5_maxgap=0.15 midlayer5_prefgap=0.149 midlayer5_minwidth=0.1 midlayer5_maxwidth=0.12 midlayer5_prefwidth=0.1 midlayer8_maxgap=0.15 midlayer8_prefgap=0.149 midlayer8_minwidth=0.1 midlayer8_maxwidth=0.12 midlayer8_prefwidth=0.1 midlayer13_maxgap=0.15 midlayer13_prefgap=0.149 midlayer13_minwidth=0.1 midlayer13_maxwidth=0.12 midlayer13_prefwidth=0.1 bottomlayer_mingap=0.2 bottomlayer_maxgap=0.22 bottomlayer_prefgap=0.21 bottomlayer_minwidth=0.1 bottomlayer_maxwidth=0.12 bottomlayer_prefwidth=0.1 impedanceprofiledriven=TRUE impedanceprofileid={1AFD27EA-460E-472B-BC44-4C5C59E93A8B} maxuncoupledlength=0.2 // Differential pair 86 Ohm
DiffPairsRouting Diff100 [InDifferentialPairClass('Diff_100')] p6: maxlimit=0.254 minlimit=0.127 mostfreqgap=0.254 toplayer_maxgap=0.127 toplayer_prefgap=0.127 toplayer_minwidth=0.045 toplayer_maxwidth=0.088 toplayer_prefwidth=0.045 midlayer1_maxgap=0.127 midlayer1_prefgap=0.127 midlayer1_minwidth=0.072 midlayer1_maxwidth=0.073 midlayer1_prefwidth=0.073 midlayer2_maxgap=0.127 midlayer2_prefgap=0.127 midlayer2_minwidth=0.072 midlayer2_maxwidth=0.073 midlayer2_prefwidth=0.073 midlayer5_maxgap=0.127 midlayer5_prefgap=0.127 midlayer5_minwidth=0.072 midlayer5_maxwidth=0.073 midlayer5_prefwidth=0.073 midlayer6_maxgap=0.127 midlayer6_prefgap=0.127 midlayer6_minwidth=0.072 midlayer6_maxwidth=0.073 midlayer6_prefwidth=0.073 midlayer7_maxgap=0.127 midlayer7_prefgap=0.127 midlayer7_minwidth=0.053 midlayer7_maxwidth=0.058 midlayer7_prefwidth=0.053 midlayer8_maxgap=0.127 midlayer8_prefgap=0.127 midlayer8_minwidth=0.072 midlayer8_maxwidth=0.073 midlayer8_prefwidth=0.073 midlayer13_maxgap=0.127 midlayer13_prefgap=0.127 midlayer13_minwidth=0.072 midlayer13_maxwidth=0.073 midlayer13_prefwidth=0.073 midlayer14_maxgap=0.127 midlayer14_prefgap=0.127 midlayer14_minwidth=0.053 midlayer14_maxwidth=0.058 midlayer14_prefwidth=0.053 bottomlayer_maxgap=0.127 bottomlayer_prefgap=0.127 bottomlayer_minwidth=0.045 bottomlayer_maxwidth=0.088 bottomlayer_prefwidth=0.045 impedanceprofiledriven=TRUE impedanceprofileid={3149E961-6C2D-4C90-A41E-90A05D6C6F09} maxuncoupledlength=12.7 // Differential 100 Ohm
DiffPairsRouting "Diff 90" [InDifferentialPairClass('Diff_90')] p7: maxlimit=0.31 minlimit=0.127 mostfreqgap=0.254 toplayer_prefgap=0.31 toplayer_minwidth=0.018 toplayer_maxwidth=0.112 toplayer_prefwidth=0.1 midlayer2_maxgap=0.262 midlayer2_prefgap=0.262 midlayer2_minwidth=0.011 midlayer2_maxwidth=0.1 midlayer2_prefwidth=0.1 midlayer5_maxgap=0.262 midlayer5_prefgap=0.262 midlayer5_minwidth=0.011 midlayer5_maxwidth=0.1 midlayer5_prefwidth=0.1 midlayer8_maxgap=0.262 midlayer8_prefgap=0.262 midlayer8_minwidth=0.011 midlayer8_maxwidth=0.1 midlayer8_prefwidth=0.1 midlayer13_maxgap=0.262 midlayer13_prefgap=0.262 midlayer13_minwidth=0.011 midlayer13_maxwidth=0.1 midlayer13_prefwidth=0.1 bottomlayer_prefgap=0.31 bottomlayer_minwidth=0.018 bottomlayer_maxwidth=0.112 bottomlayer_prefwidth=0.1 impedanceprofiledriven=TRUE impedanceprofileid={1D82871A-FACB-482B-B08F-C93C2922060F} maxuncoupledlength=12.7 // Differential 90 Ohm
HoleSize DrillHole [All] p1: absolutevalues=TRUE maxlimit=5 minlimit=0.1 maxpercent=80.000 minpercent=20.000
HoleToHoleClearance [All] p1: gap=0.1 allowstackedmicrovias=TRUE
MatchedLengths MatchedLengths_DDR_CLOCKS_STROBES [InxSignalClass('ADDR_PP1') OR InxSignalClass('ADDR_PP2') OR InxSignalClass('ADDR_PP3') OR InxSignalClass('ADDR_PP4') OR InxSignalClass('DATA_BL0') OR InxSignalClass('DATA_BL1') OR InxSignalClass('DATA_BL2') OR InxSignalClass('DATA_BL3') OR InxSignalClass('DATA_BL4') OR InxSignalClass('DATA_BL5') OR InxSignalClass('DATA_BL6') OR InxSignalClass('DATA_BL7')] p1: tolerance=0.305 checknetsindiffpair=TRUE checkdiffpairvsdiffpair=FALSE checkxsignals=FALSE checkothers=FALSE
MatchedLengths MatchedLengths_DATA_BL7 [InxSignalClass('DATA_BL7')] p2: tolerance=1.473 checknetsindiffpair=FALSE checkdiffpairvsdiffpair=TRUE checkxsignals=TRUE checkothers=TRUE
MatchedLengths MatchedLengths_DATA_BL6 [InxSignalClass('DATA_BL6')] p3: tolerance=1.473 checknetsindiffpair=FALSE checkdiffpairvsdiffpair=TRUE checkxsignals=TRUE checkothers=TRUE
MatchedLengths MatchedLengths_DATA_BL5 [InxSignalClass('DATA_BL5')] p4: tolerance=1.473 checknetsindiffpair=FALSE checkdiffpairvsdiffpair=TRUE checkxsignals=TRUE checkothers=TRUE
MatchedLengths MatchedLengths_DATA_BL4 [InxSignalClass('DATA_BL4')] p5: tolerance=1.473 checknetsindiffpair=FALSE checkdiffpairvsdiffpair=TRUE checkxsignals=TRUE checkothers=TRUE
MatchedLengths MatchedLengths_DATA_BL3 [InxSignalClass('DATA_BL3')] p6: tolerance=1.473 checknetsindiffpair=FALSE checkdiffpairvsdiffpair=TRUE checkxsignals=TRUE checkothers=TRUE
MatchedLengths MatchedLengths_DATA_BL2 [InxSignalClass('DATA_BL2')] p7: tolerance=1.473 checknetsindiffpair=FALSE checkdiffpairvsdiffpair=TRUE checkxsignals=TRUE checkothers=TRUE
MatchedLengths MatchedLengths_DATA_BL1 [InxSignalClass('DATA_BL1')] p8: tolerance=1.473 checknetsindiffpair=FALSE checkdiffpairvsdiffpair=TRUE checkxsignals=TRUE checkothers=TRUE
MatchedLengths MatchedLengths_DATA_BL0 [InxSignalClass('DATA_BL0')] p9: tolerance=1.473 checknetsindiffpair=FALSE checkdiffpairvsdiffpair=TRUE checkxsignals=TRUE checkothers=TRUE
MatchedLengths MatchedLengths_ADDR_PP4 [InxSignalClass('ADDR_PP4')] p10: tolerance=1.194 checknetsindiffpair=FALSE checkdiffpairvsdiffpair=TRUE checkxsignals=TRUE checkothers=TRUE
MatchedLengths MatchedLengths_ADDR_PP3 [InxSignalClass('ADDR_PP3')] p11: tolerance=1.194 checknetsindiffpair=FALSE checkdiffpairvsdiffpair=TRUE checkxsignals=TRUE checkothers=TRUE
MatchedLengths MatchedLengths_ADDR_PP2 [InxSignalClass('ADDR_PP2')] p12: tolerance=1.194 checknetsindiffpair=FALSE checkdiffpairvsdiffpair=TRUE checkxsignals=TRUE checkothers=TRUE
MatchedLengths MatchedLengths_ADDR_PP1 [InxSignalClass('ADDR_PP1')] p13: tolerance=1.194 checknetsindiffpair=FALSE checkdiffpairvsdiffpair=TRUE checkxsignals=TRUE checkothers=TRUE
MatchedLengths SFP_Data [InNetClass('SFP_diff')] p14: tolerance=0.305 checknetsindiffpair=FALSE checkdiffpairvsdiffpair=TRUE checkxsignals=TRUE checkothers=TRUE
MatchedLengths DiferentialPairSkew [All] p15: tolerance=25.4 checknetsindiffpair=TRUE checkdiffpairvsdiffpair=FALSE checkxsignals=FALSE checkothers=FALSE
MatchedLengths RAM_Data_to_DQS [InNetClass('Lenght_DQS_to_Data')] p16 off: tolerance=25.4 checknetsindiffpair=FALSE checkdiffpairvsdiffpair=TRUE checkxsignals=TRUE checkothers=TRUE
MatchedLengths RAM_DQS_to_CK [InNetClass('Lenght_DQS_to_CK')] p17 off: tolerance=25.4 checknetsindiffpair=FALSE checkdiffpairvsdiffpair=TRUE checkxsignals=TRUE checkothers=TRUE
MatchedLengths MatchedLengths_DDR_DQS [InNetClass('RAM_DQS_Strobe')] p18 off: tolerance=0.305 checknetsindiffpair=TRUE checkdiffpairvsdiffpair=FALSE checkxsignals=FALSE checkothers=FALSE
MatchedLengths RAM_Addr_LenghMatch [InNetClass('RAM_Adress')] p19 off: tolerance=0.305 checknetsindiffpair=FALSE checkdiffpairvsdiffpair=TRUE checkxsignals=TRUE checkothers=TRUE
MatchedLengths Ram_Addr_Com_Ctrl_to_CK [InNetClass('Lenght_CK_to_Addr')] p20 off: tolerance=0.305 checknetsindiffpair=FALSE checkdiffpairvsdiffpair=TRUE checkxsignals=TRUE checkothers=TRUE
MatchedLengths RAM_MatchedLengths_DATA_IO [InNetClass('RAM_Data_IO')] p21 off: tolerance=0.305 checknetsindiffpair=FALSE checkdiffpairvsdiffpair=TRUE checkxsignals=TRUE checkothers=TRUE
MinimumAnnularRing DefRing [All] p1: minimumring=0.15
MinimumSolderMaskSliver [All] p1: minsoldermaskwidth=0.1
PlaneClearance [All] p1: clearance=0.2
PlaneConnect [All] p1: planeconnectstyle=Direct reliefexpansion=0.508 reliefentries=4 reliefconductorwidth=0.254 reliefairgap=0.254
PolygonConnect PowerPolygon [All] p1: connectstyle=Direct reliefconductorwidth=0.254 reliefentries=4 polygonreliefangle="90 Angle" airgapwidth=0.254
PolygonConnect PolygonConnect_1 [All] p2 off: connectstyle=Relief reliefconductorwidth=0.254 reliefentries=4 polygonreliefangle="90 Angle" airgapwidth=0.254
RoomDefinition RAMStubRoom_Addr [not All] p1: confinementstyle=ConfineIn formatcopy=TRUE lockcomponents=FALSE outline 158.259,345.172 185.298,345.172 185.298,330.46 158.259,330.46
RoomDefinition RAM_CLK [False] p2: confinementstyle=ConfineIn formatcopy=TRUE lockcomponents=FALSE outline 165.251,341.085 207.682,341.085 207.682,327.035 165.251,327.035
RoomDefinition FPGA_Room [Not All] p3: confinementstyle=ConfineIn formatcopy=TRUE lockcomponents=FALSE outline 161.397,318.539 192.397,318.539 192.397,287.539 161.397,287.539
RoomDefinition RAM_1 [Not All] p4: confinementstyle=ConfineIn formatcopy=TRUE lockcomponents=FALSE outline 199.382,341.335 207.932,341.335 207.932,326.785 199.382,326.785
RoomDefinition RAM_2 [Not All] p5: confinementstyle=ConfineIn formatcopy=TRUE lockcomponents=FALSE outline 187.922,341.335 196.472,341.335 196.472,326.785 187.922,326.785
RoomDefinition Ram_4 [Not All] p6: confinementstyle=ConfineIn formatcopy=TRUE lockcomponents=FALSE outline 176.461,341.335 185.011,341.335 185.011,326.785 176.461,326.785
RoomDefinition RAM_3 [Not All] p7: confinementstyle=ConfineIn formatcopy=TRUE lockcomponents=FALSE outline 165.001,341.335 173.551,341.335 173.551,326.785 165.001,326.785
RoutingTopology RoutingTopology_DDRAddressAndControls [InNetClass('DDR_AddressAndControls')] p1: topology=Daisy_Simple
RoutingTopology [All] p2: topology=Shortest
RoutingVias BackDrilled_1-5 [InDrillLayerPair('[BD] L5 (Sign) - L16')] p1: holewidth=0.2 width=0.5 viastyle="Through Hole" minholewidth=0.2 minwidth=0.5 maxholewidth=0.2 maxwidth=0.5
RoutingVias BackDrilled_1-14 [InDrillLayerPair('[BD] L14 (Sign) - L16')] p2: holewidth=0.2 width=0.5 viastyle="Through Hole" minholewidth=0.2 minwidth=0.5 maxholewidth=0.2 maxwidth=0.5
RoutingVias BackDrilled_1-12 [InDrillLayerPair('[BD] L12 (Sign) - L16')] p3: holewidth=0.2 width=0.5 viastyle="Through Hole" minholewidth=0.2 minwidth=0.5 maxholewidth=0.2 maxwidth=0.5
RoutingVias Vi14-16 [InDrillLayerPair('[UVIA] L14 (Sign) - L16')] p4: holewidth=0.127 width=0.35 viastyle="Through Hole" minholewidth=0.1 minwidth=0.2 maxholewidth=0.127 maxwidth=0.35
RoutingVias UVia1-2 [InDrillLayerPair('[UVIA] L1 - L2 (GND)')] p5: holewidth=0.127 width=0.35 viastyle="Through Hole" minholewidth=0.127 minwidth=0.35 maxholewidth=0.127 maxwidth=0.35
RoutingVias UVia1-3 [InDrillLayerPair('[UVIA] L1 - L3 (Sign)')] p6: holewidth=0.127 width=0.35 viastyle="Through Hole" minholewidth=0.1 minwidth=0.2 maxholewidth=0.127 maxwidth=0.35
RoutingVias UVia16-15 [InDrillLayerPair('[UVIA] L15 (GND) - L16')] p7: holewidth=0.127 width=0.35 viastyle="Through Hole" minholewidth=0.1 minwidth=0.2 maxholewidth=0.127 maxwidth=0.35
RoutingVias UVia14-15 [InDrillLayerPair('No Drill Pair')] p8: holewidth=0.127 width=0.35 viastyle="Through Hole" minholewidth=0.127 minwidth=0.35 maxholewidth=0.127 maxwidth=0.35
RoutingVias Diff_Pair_Via [InDifferentialPairClass('All Differential Pairs')] p9: holewidth=0.2 width=0.4 viastyle="Through Hole" minholewidth=0.127 minwidth=0.35 maxholewidth=0.3 maxwidth=0.5
RoutingVias [All] p10: holewidth=0.2 width=0.5 viastyle="Through Hole" minholewidth=0.1 minwidth=0.2 maxholewidth=2 maxwidth=2.25
ShortCircuit [InPadClass('All Pads') vs InPadClass('All Pads')] p1: allowed=FALSE
SilkToSilkClearance [All] p1: silktosilkclearance=0.1
SilkToSolderMaskClearance [IsPad] p1: minsilkscreentomaskgap=0 clearancetoexposedcopper=TRUE
SolderMaskExpansion [All] p1: expansion=0.102
Width RAM_Address_50 [InNetClass('Single_36_39_50_Adr') and (WithinRoom('RAM_CLK')or WithinRoom('FPGA_Room'))] p1: maxlimit=0.254 minlimit=0.062 preferedwidth=0.254 toplayer_minwidth=0.112 toplayer_maxwidth=0.116 toplayer_prefwidth=0.112 midlayer1_minwidth=0.092 midlayer1_maxwidth=0.092 midlayer1_prefwidth=0.092 midlayer2_minwidth=0.092 midlayer2_maxwidth=0.092 midlayer2_prefwidth=0.092 midlayer5_minwidth=0.092 midlayer5_maxwidth=0.092 midlayer5_prefwidth=0.092 midlayer6_minwidth=0.092 midlayer6_maxwidth=0.092 midlayer6_prefwidth=0.092 midlayer7_maxwidth=0.069 midlayer7_prefwidth=0.062 midlayer8_minwidth=0.092 midlayer8_maxwidth=0.092 midlayer8_prefwidth=0.092 midlayer13_minwidth=0.092 midlayer13_maxwidth=0.092 midlayer13_prefwidth=0.092 midlayer14_maxwidth=0.069 midlayer14_prefwidth=0.062 bottomlayer_minwidth=0.112 bottomlayer_maxwidth=0.116 bottomlayer_prefwidth=0.112 impedanceprofiledriven=TRUE impedanceprofileid={C52096D4-C36E-4BDB-BB83-9E54FFDADA41} minimp=50.000000 maximp=50.000000 favimp=50.000000
Width RAM_StubAddress39 [InNetClass('Single_36_39_50_Adr') and WithinRoom('RAMStubRoom_Addr')] p2: maxlimit=0.254 minlimit=0.105 preferedwidth=0.254 toplayer_minwidth=0.155 toplayer_maxwidth=0.186 toplayer_prefwidth=0.155 midlayer1_minwidth=0.151 midlayer1_maxwidth=0.151 midlayer1_prefwidth=0.151 midlayer2_minwidth=0.151 midlayer2_maxwidth=0.151 midlayer2_prefwidth=0.151 midlayer5_minwidth=0.151 midlayer5_maxwidth=0.151 midlayer5_prefwidth=0.151 midlayer6_minwidth=0.151 midlayer6_maxwidth=0.151 midlayer6_prefwidth=0.151 midlayer7_maxwidth=0.115 midlayer7_prefwidth=0.105 midlayer8_minwidth=0.151 midlayer8_maxwidth=0.151 midlayer8_prefwidth=0.151 midlayer13_minwidth=0.151 midlayer13_maxwidth=0.151 midlayer13_prefwidth=0.151 midlayer14_maxwidth=0.115 midlayer14_prefwidth=0.105 bottomlayer_minwidth=0.155 bottomlayer_maxwidth=0.186 bottomlayer_prefwidth=0.155 impedanceprofiledriven=TRUE impedanceprofileid={9B370C13-2427-420A-A153-D73BE69366B2} minimp=50.000000 maximp=50.000000 favimp=50.000000
Width RAM_Addr36 [InNetClass('Single_36_39_50_Adr')and not (WithinRoom('RAM_CLK')or WithinRoom('FPGA_Room'))] p3: maxlimit=0.254 minlimit=0.122 preferedwidth=0.254 toplayer_minwidth=0.182 toplayer_maxwidth=0.212 toplayer_prefwidth=0.182 midlayer1_minwidth=0.173 midlayer1_maxwidth=0.173 midlayer1_prefwidth=0.173 midlayer2_minwidth=0.173 midlayer2_maxwidth=0.173 midlayer2_prefwidth=0.173 midlayer5_minwidth=0.173 midlayer5_maxwidth=0.173 midlayer5_prefwidth=0.173 midlayer6_minwidth=0.173 midlayer6_maxwidth=0.173 midlayer6_prefwidth=0.173 midlayer7_maxwidth=0.133 midlayer7_prefwidth=0.122 midlayer8_minwidth=0.173 midlayer8_maxwidth=0.173 midlayer8_prefwidth=0.173 midlayer13_minwidth=0.173 midlayer13_maxwidth=0.173 midlayer13_prefwidth=0.173 midlayer14_maxwidth=0.133 midlayer14_prefwidth=0.122 bottomlayer_minwidth=0.182 bottomlayer_maxwidth=0.212 bottomlayer_prefwidth=0.182 impedanceprofiledriven=TRUE impedanceprofileid={2EC469A3-C20B-4F07-A421-E0D2C58D58A8} minimp=50.000000 maximp=50.000000 favimp=50.000000
Width Single_Ram_CLK [InNetClass('RAM_Clock_Signal')] p4: maxlimit=0.152 minlimit=0.102 preferedwidth=0.127
Width Single_RAM_Com [InNetClass('RAM_Adress')] p5: maxlimit=0.254 minlimit=0.068 preferedwidth=0.254 toplayer_minwidth=0.116 toplayer_maxwidth=0.211 toplayer_prefwidth=0.184 midlayer1_minwidth=0.092 midlayer1_maxwidth=0.173 midlayer1_prefwidth=0.151 midlayer2_minwidth=0.092 midlayer2_maxwidth=0.173 midlayer2_prefwidth=0.151 midlayer3_minwidth=0.254 midlayer4_minwidth=0.254 midlayer5_minwidth=0.092 midlayer5_maxwidth=0.173 midlayer5_prefwidth=0.151 midlayer6_minwidth=0.092 midlayer6_maxwidth=0.173 midlayer6_prefwidth=0.151 midlayer7_maxwidth=0.132 midlayer7_prefwidth=0.114 midlayer8_minwidth=0.092 midlayer8_maxwidth=0.173 midlayer8_prefwidth=0.151 midlayer9_minwidth=0.092 midlayer9_prefwidth=0.151 midlayer10_minwidth=0.254 midlayer11_minwidth=0.254 midlayer12_minwidth=0.254 midlayer13_minwidth=0.092 midlayer13_maxwidth=0.173 midlayer13_prefwidth=0.151 midlayer14_maxwidth=0.132 midlayer14_prefwidth=0.114 bottomlayer_minwidth=0.116 bottomlayer_maxwidth=0.211 bottomlayer_prefwidth=0.184 minimp=50.000000 maximp=50.000000 favimp=50.000000 // Track's for Adress, comands and control
Width Single_RAM_Ten [InNet('DDR4_TEN')] p6: maxlimit=0.254 minlimit=0.068 preferedwidth=0.254 toplayer_minwidth=0.116 toplayer_maxwidth=0.211 toplayer_prefwidth=0.184 midlayer1_minwidth=0.092 midlayer1_maxwidth=0.173 midlayer1_prefwidth=0.151 midlayer2_minwidth=0.092 midlayer2_maxwidth=0.173 midlayer2_prefwidth=0.151 midlayer3_minwidth=0.254 midlayer4_minwidth=0.254 midlayer5_minwidth=0.092 midlayer5_maxwidth=0.173 midlayer5_prefwidth=0.151 midlayer6_minwidth=0.092 midlayer6_maxwidth=0.173 midlayer6_prefwidth=0.151 midlayer7_maxwidth=0.132 midlayer7_prefwidth=0.114 midlayer8_minwidth=0.092 midlayer8_maxwidth=0.173 midlayer8_prefwidth=0.151 midlayer9_minwidth=0.092 midlayer9_prefwidth=0.151 midlayer10_minwidth=0.254 midlayer11_minwidth=0.254 midlayer12_minwidth=0.254 midlayer13_minwidth=0.092 midlayer13_maxwidth=0.173 midlayer13_prefwidth=0.151 midlayer14_maxwidth=0.132 midlayer14_prefwidth=0.114 bottomlayer_minwidth=0.116 bottomlayer_maxwidth=0.211 bottomlayer_prefwidth=0.184 minimp=50.000000 maximp=50.000000 favimp=50.000000 // Track's for Adress, comands and control
Width SingleRam_Data [InNetClass('RAM_Data_IO')] p7: maxlimit=0.254 minlimit=0.068 preferedwidth=0.254 toplayer_minwidth=0.116 toplayer_maxwidth=0.211 toplayer_prefwidth=0.184 midlayer1_minwidth=0.092 midlayer1_maxwidth=0.173 midlayer1_prefwidth=0.151 midlayer2_minwidth=0.092 midlayer2_maxwidth=0.173 midlayer2_prefwidth=0.151 midlayer3_minwidth=0.254 midlayer4_minwidth=0.254 midlayer5_minwidth=0.092 midlayer5_maxwidth=0.173 midlayer5_prefwidth=0.151 midlayer6_minwidth=0.092 midlayer6_maxwidth=0.173 midlayer6_prefwidth=0.151 midlayer7_maxwidth=0.132 midlayer7_prefwidth=0.114 midlayer8_minwidth=0.092 midlayer8_maxwidth=0.173 midlayer8_prefwidth=0.151 midlayer9_minwidth=0.092 midlayer9_prefwidth=0.151 midlayer10_minwidth=0.254 midlayer11_minwidth=0.254 midlayer12_minwidth=0.254 midlayer13_minwidth=0.092 midlayer13_maxwidth=0.173 midlayer13_prefwidth=0.151 midlayer14_maxwidth=0.132 midlayer14_prefwidth=0.114 bottomlayer_minwidth=0.116 bottomlayer_maxwidth=0.211 bottomlayer_prefwidth=0.184 minimp=50.000000 maximp=50.000000 favimp=50.000000 // Track's for comand in r
Width Single45 [InNetClass('Single_45')] p8: maxlimit=0.198 minlimit=0.079 preferedwidth=0.198 toplayer_minwidth=0.113 toplayer_maxwidth=0.143 toplayer_prefwidth=0.113 midlayer1_minwidth=0.115 midlayer1_maxwidth=0.115 midlayer1_prefwidth=0.115 midlayer2_minwidth=0.115 midlayer2_maxwidth=0.115 midlayer2_prefwidth=0.115 midlayer3_minwidth=0.198 midlayer4_minwidth=0.198 midlayer5_minwidth=0.115 midlayer5_maxwidth=0.115 midlayer5_prefwidth=0.115 midlayer6_minwidth=0.115 midlayer6_maxwidth=0.115 midlayer6_prefwidth=0.115 midlayer7_maxwidth=0.087 midlayer7_prefwidth=0.079 midlayer8_minwidth=0.115 midlayer8_maxwidth=0.115 midlayer8_prefwidth=0.115 midlayer9_minwidth=0.133 midlayer9_maxwidth=0.133 midlayer9_prefwidth=0.133 midlayer10_minwidth=0.198 midlayer11_minwidth=0.198 midlayer12_minwidth=0.133 midlayer12_maxwidth=0.133 midlayer12_prefwidth=0.133 midlayer13_minwidth=0.115 midlayer13_maxwidth=0.115 midlayer13_prefwidth=0.115 midlayer14_maxwidth=0.087 midlayer14_prefwidth=0.079 bottomlayer_minwidth=0.113 bottomlayer_maxwidth=0.143 bottomlayer_prefwidth=0.113 impedanceprofiledriven=TRUE impedanceprofileid={F22BED46-E16F-4103-815A-6A081543B36A} minimp=50.000000 maximp=50.000000 favimp=50.000000 // Single line impedance 45 Ohm
Width "Single 50" [InNetClass('Single_50')] p9: maxlimit=0.254 minlimit=0.062 preferedwidth=0.254 toplayer_minwidth=0.112 toplayer_maxwidth=0.116 toplayer_prefwidth=0.112 midlayer1_minwidth=0.092 midlayer1_maxwidth=0.092 midlayer1_prefwidth=0.092 midlayer2_minwidth=0.092 midlayer2_maxwidth=0.092 midlayer2_prefwidth=0.092 midlayer5_minwidth=0.092 midlayer5_maxwidth=0.092 midlayer5_prefwidth=0.092 midlayer6_minwidth=0.092 midlayer6_maxwidth=0.092 midlayer6_prefwidth=0.092 midlayer7_maxwidth=0.069 midlayer7_prefwidth=0.062 midlayer8_minwidth=0.092 midlayer8_maxwidth=0.092 midlayer8_prefwidth=0.092 midlayer13_minwidth=0.092 midlayer13_maxwidth=0.092 midlayer13_prefwidth=0.092 midlayer14_maxwidth=0.069 midlayer14_prefwidth=0.062 bottomlayer_minwidth=0.112 bottomlayer_maxwidth=0.116 bottomlayer_prefwidth=0.112 impedanceprofiledriven=TRUE impedanceprofileid={C52096D4-C36E-4BDB-BB83-9E54FFDADA41} minimp=50.000000 maximp=50.000000 favimp=50.000000 checkconnectedcopper=TRUE // Single impedance line 50 Ohm
Width [InNetClass('SFP_diff')] p10 off: maxlimit=0.254 minlimit=0.254 preferedwidth=0.254
Width Power [All] p11: maxlimit=2 minlimit=0.2 preferedwidth=0.5
20 further rules are at their usual default settings.

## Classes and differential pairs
differential pair class Diff_86: DDR4_CK
differential pair class Diff_76: DDR4_CK
component class GND: J31
component class I2C_Expander_16: C311_I2C_Expander_16 U35_I2C_Expander_16
component class I2C_Expander_15: C311_I2C_Expander_15
component class I2C_Expander_14: C311_I2C_Expander_14
component class I2C_Expander_13: C311_I2C_Expander_13
component class I2C_Expander_12: C311_I2C_Expander_12
component class I2C_Expander_11: C311_I2C_Expander_11
component class I2C_Expander_10: C311_I2C_Expander_10
component class I2C_Expander?: C311_I2C_Expander?
component class I2C_Bridge_2: C303_I2C_Bridge_2 R3_I2C_Bridge_2 R4_I2C_Bridge_2 R5_I2C_Bridge_2 R6_I2C_Bridge_2 R7_I2C_Bridge_2 R8_I2C_Bridge_2 R9_I2C_Bridge_2 R10_I2C_Bridge_2 R223_I2C_Bridge_2 R224_I2C_Bridge_2 R225_I2C_Bridge_2 R226_I2C_Bridge_2 R227_I2C_Bridge_2 R558_I2C_Bridge_2 R559_I2C_Bridge_2 R560_I2C_Bridge_2 TP1_I2C_Bridge_2 TP2_I2C_Bridge_2 TP3_I2C_Bridge_2 TP4_I2C_Bridge_2 TP5_I2C_Bridge_2 TP6_I2C_Bridge_2 TP7_I2C_Bridge_2 TP8_I2C_Bridge_2 TP9_I2C_Bridge_2 TP10_I2C_Bridge_2 TP11_I2C_Bridge_2 TP12_I2C_Bridge_2 TP13_I2C_Bridge_2 TP14_I2C_Bridge_2 TP15_I2C_Bridge_2 TP16_I2C_Bridge_2 TP17_I2C_Bridge_2 TP18_I2C_Bridge_2 U3_I2C_Bridge_2
differential pair class Diff_90: DDR4_CK USB_D USB_RX USB_RX_C USB_TX USB_TX_C
net class uSD_to_MIO: CD_H DIR_CMD DIR_DAT0_H DIR_DAT1_H uSD_CLK uSD_CMD uSD_D0 uSD_D1 uSD_D2 uSD_D3 uSD_D4
net class uSD_to_Driv: CD_H CMD_SD DATA0_SD DATA1_SD DATA2_SD DATA3_SD SD_Card_CLK
net class USB_2.0: USB_D_N
net class USB3._to_C: USB_RX_C_N USB_RX_C_P USB_TX_C_N USB_TX_C_P
net class USB3._C_to_FPGA: USB_RX_N USB_RX_P USB_TX_N USB_TX_P
net class Single_45: USB_D_N USB_D_P USB_RX_C_N USB_RX_C_P USB_RX_N USB_RX_P USB_TX_C_N USB_TX_C_P USB_TX_N USB_TX_P
net class SGMII_DATA_TO_C: SGMI_Rx_N SGMI_Rx_P SGMI_Tx_N SGMI_Tx_P
net class SGMII_DATA_C_FPGA: SGMI_C_Rx_N SGMI_C_Rx_P SGMI_C_Tx_N SGMI_C_Tx_P
net class Power_Line_40A: 0.85V@40A_INA US+_Vcc_PS_IntFp
net class Power_Line_20A: 3V3_RAIL RAM_Vcc1V2 Vout1_1 Vout2_1
net class Power_Line_10A: 3.3Vaux 5V_RAIL 12V_HiSpeed Vout1_2 Vout_5V@10A_INA
net class Power_Line_2A: 0V9@1A_REG3 0V85@2A 1V0@1.5A 1V8@0.5A_ADC_filtered 1V8@1.5A 2V5@1.5A 3.3V_LN_1 3.3V_Stable_1 3.3V_Stable_2 3.3V_Stable_3 3V3_RAIL 12V_PCIE0 12V_PCIE1 12V_PCIE2 12V_PCIE3 12V_PCIE4 +12V_PCIE0 +12V_PCIE1 +12V_PCIE2 +12V_PCIE3 +12V_PCIE4 FTDI_5V FTDI_VBUS FTDI_VccIO NetC568_2 NetC674_2
net class NVMe_REFCLK: CLK_NVME_Conn_N CLK_NVME_Conn_P
net class NVMe_DATA: NVMe_Rx_0_N NVMe_Rx_0_P NVMe_Rx_1_N NVMe_Rx_1_P NVMe_Tx_0_N NVMe_Tx_0_P NVMe_Tx_1_N NVMe_Tx_1_P
net class eMMC_Data: eMMC_data0 eMMC_data1 eMMC_data2 eMMC_data3 eMMC_data4 eMMC_data5 eMMC_data6 eMMC_data7
net class eMMC_Cmd: eMMC_clk eMMC_cmd eMMC_rst
net class DATA_ETH_TO_PHY: TD_A_N TD_A_P TD_B_N TD_B_P TD_C_N TD_C_P TD_D_N TD_D_P
component class µSD: C544 C545 C546 C547 FB29 J28 R381 R382 R383 U47
component class USB3.0: C537 C538 C539 C540 C541 C542 C543 C728 C729 C730 C731 C732 C733 C734 C735 C736 C737 D13 D14 FB26 FB27 FB28 R376 R377 R378 R379 R380 R490 R491 U45 U46 U74 X7
component class U_Expander_RESET: R746 R747 R748 R749 R750 R751 R752 R753 R754 R755 R756 R757 R758 R759 R760 R761 R762 R763
component class U_CAN: C585 P6 R446 R447 U63 U75
component class NVMe: J27 R541 R542
component class "Gigabit Eth": C471 C472 C473 C474 C475 C476 C479 C480 C481 C482 C483 C484 C485 C486 C487 C488 C489 C490 C491 C492 C493 C494 C495 C496 C497 C498 C499 C500 C501 C502 C503 C504 C505 C506 C507 C508 C509 C510 C511 C512 C513 C514 C790 D1 D2 D3 D4 R319 R320 R321 R322 R323 R324 R325 R326 R327 R328 R329 R330 R331 R332 R333 R334 R335 R336 R337 R338 R709 R710 R711 R712 R713 R714 R715 S7 T21 U39 U76 X4
component class Flash_Memory: C515 C516 C517 C518 C519 C520 C521 C522 C523 C524 C586 C587 FB25 R339 R340 R341 R342 R343 R344 R345 U40 U41 U42
component class Debug: C558 C559 C560 C658 C659 C660 C661 C662 C663 C664 C665 C666 C667 C668 C669 C670 C671 C672 C673 C791 C792 D15 FB31 FB32 FB43 FB44 P12 R401 R402 R403 R404 R405 R406 R407 R408 R409 R410 R411 R412 R413 R414 R415 R416 R417 R418 R419 R420 R421 R422 R423 R424 R635 R636 R637 R638 R639 R640 R641 R642 R643 R721 R722 R723 R724 R725 R726 R727 R728 R729 R730 R731 R732 R733 R734 U53 U54 U55 U56 U57 U77 U78 U79 X8
component class 5V_to_3V3_for_FTDI: C563_5V_to_3V3_for_FTDI C564_5V_to_3V3_for_FTDI C565_5V_to_3V3_for_FTDI C566_5V_to_3V3_for_FTDI C567_5V_to_3V3_for_FTDI R430_5V_to_3V3_for_FTDI R431_5V_to_3V3_for_FTDI R432_5V_to_3V3_for_FTDI U59_5V_to_3V3_for_FTDI
component class I2C_Expander2: C311_I2C_Expander2 U35_I2C_Expander2
component class I2C_Expander1: C311_I2C_Expander1 U35_I2C_Expander1
component class U_FPGA_Decoupling: C738 C739 C740 C741 C742 C743 C744 C745 C746 C747 C748 C749 C750 C751 C752 C753 C754 C755 C756 C757 C758 C759 C760 C761 C762 C763 C764 C765
net class NVME_DATA_BANK: NVME_C_RX_1_P NVME_C_RX_O_N NVME_C_RX_O_P NVME_C_TX_1_N NVME_C_TX_1_P NVME_C_TX_O_N NVME_C_TX_O_P
component class U_ST1L08_5V_0V6: C720 C721 C722 C723 R689 R690 R691 U73
component class U_Pomiar_napiecia_high_curr: C310 R617 U72
component class U_UM78M_12_8V: C713 C714 U71
component class U_TPS7A88_3V3_1V8_0V9V@2x1A: C705 C706 C707 C708 C709 C710 C711 C712 R671 R672 R673 R674 R676 R745 U70
component class U_ADP1741_3V3_0V85: C674 C675 C676 C719 FB45 R435 R644 R645 R646 R668 U69
component class LowCurr: C304 C305 C306 C307 C308 C354 C355 C603 C604 C605 C606 C607 C610 C611 C612 C613 C614 C615 C616 C617 C618 C619 C620 C621 C622 C623 C624 C625 C626 D16 D17 D18 D19 L13 L15 L16 L17 L18 R113 R114 R212 R214 R216 R218 R220 R274 R284 R305 R308 R309 U19 U67
component class U_Detektor_otwarcia: BT1 BT? C609 C678 C679 C680 D20 D21 D22 D23 R647 R648 R649 R650 R651 R652 R653 R654 R655 R656 R657 R658 T22 T23 T24 T25 T26 T27 T28 T29 T30 T31
net class RAM_DQS_Strobe: DDR4_DQS_0_N DDR4_DQS_0_P DDR4_DQS_1_N DDR4_DQS_1_P DDR4_DQS_2_N DDR4_DQS_2_P DDR4_DQS_3_N DDR4_DQS_3_P DDR4_DQS_4_N DDR4_DQS_4_P DDR4_DQS_5_N DDR4_DQS_5_P DDR4_DQS_6_N DDR4_DQS_6_P DDR4_DQS_7_N DDR4_DQS_7_P DDR4_DQS_8_N DDR4_DQS_8_P
net class RAM_Data_IO: DDR4_DM0 DDR4_DM1 DDR4_DM2 DDR4_DM3 DDR4_DM4 DDR4_DM5 DDR4_DM6 DDR4_DM7 DDR4_DQ0 DDR4_DQ1 DDR4_DQ2 DDR4_DQ3 DDR4_DQ4 DDR4_DQ5 DDR4_DQ6 DDR4_DQ7 DDR4_DQ8 DDR4_DQ9 DDR4_DQ10 DDR4_DQ11 DDR4_DQ12 DDR4_DQ13 DDR4_DQ14 DDR4_DQ15 DDR4_DQ16 DDR4_DQ17 DDR4_DQ18 DDR4_DQ19 DDR4_DQ20 DDR4_DQ21 DDR4_DQ22 DDR4_DQ23 DDR4_DQ24 DDR4_DQ25 DDR4_DQ26 DDR4_DQ27 DDR4_DQ28 DDR4_DQ29 DDR4_DQ30 DDR4_DQ31 DDR4_DQ32 DDR4_DQ33 DDR4_DQ34 DDR4_DQ35 DDR4_DQ36 DDR4_DQ37 DDR4_DQ38 DDR4_DQ39 DDR4_DQ40 DDR4_DQ41 DDR4_DQ42 DDR4_DQ43 DDR4_DQ44 DDR4_DQ45 DDR4_DQ46 DDR4_DQ47 DDR4_DQ48 DDR4_DQ49 DDR4_DQ50 DDR4_DQ51 DDR4_DQ52 DDR4_DQ53 DDR4_DQ54 DDR4_DQ55 DDR4_DQ56 DDR4_DQ57 DDR4_DQ58 DDR4_DQ59 DDR4_DQ60 DDR4_DQ61 DDR4_DQ62 DDR4_DQ63
net class Power_Line_1A: 3.3V_PS_Config 12V_HiSpeed ADP1741_3.6V FPGA_Vcc_HD NetD16_2 NetD17_1 NetD17_2 NetD18_1 NetD18_2 NetD19_1 NetD19_2 Power_3.3_1 Power_3.3_2 US+_Vcc_PS_DDR_504
net class Lenght_DQS_to_Data: DDR4_DM0 DDR4_DM1 DDR4_DM2 DDR4_DM3 DDR4_DM4 DDR4_DM5 DDR4_DM6 DDR4_DM7 DDR4_DQ0 DDR4_DQ1 DDR4_DQ2 DDR4_DQ3 DDR4_DQ4 DDR4_DQ5 DDR4_DQ6 DDR4_DQ7 DDR4_DQ8 DDR4_DQ9 DDR4_DQ10 DDR4_DQ11 DDR4_DQ12 DDR4_DQ13 DDR4_DQ14 DDR4_DQ15 DDR4_DQ16 DDR4_DQ17 DDR4_DQ18 DDR4_DQ19 DDR4_DQ20 DDR4_DQ21 DDR4_DQ22 DDR4_DQ23 DDR4_DQ24 DDR4_DQ25 DDR4_DQ26 DDR4_DQ27 DDR4_DQ28 DDR4_DQ29 DDR4_DQ30 DDR4_DQ31 DDR4_DQ32 DDR4_DQ33 DDR4_DQ34 DDR4_DQ35 DDR4_DQ36 DDR4_DQ37 DDR4_DQ38 DDR4_DQ39 DDR4_DQ40 DDR4_DQ41 DDR4_DQ42 DDR4_DQ43 DDR4_DQ44 DDR4_DQ45 DDR4_DQ46 DDR4_DQ47 DDR4_DQ48 DDR4_DQ49 DDR4_DQ50 DDR4_DQ51 DDR4_DQ52 DDR4_DQ53 DDR4_DQ54 DDR4_DQ55 DDR4_DQ56 DDR4_DQ57 DDR4_DQ58 DDR4_DQ59 DDR4_DQ60 DDR4_DQ61 DDR4_DQ62 DDR4_DQ63
net class Lenght_DQS_to_CK: DDR4_DQS_0_N DDR4_DQS_0_P DDR4_DQS_1_N DDR4_DQS_1_P DDR4_DQS_2_N DDR4_DQS_2_P DDR4_DQS_3_N DDR4_DQS_3_P DDR4_DQS_4_N DDR4_DQS_4_P DDR4_DQS_5_N DDR4_DQS_5_P DDR4_DQS_6_N DDR4_DQS_6_P DDR4_DQS_7_N DDR4_DQS_7_P DDR4_DQS_8_N DDR4_DQS_8_P
net class Lenght_CK_to_Addr: DDR4_CK_N DDR4_CK_P
differential pair class Diff_76_to_90_Ram_CLK: DDR4_CK
net class RAM_Adress: DDR4_A0 DDR4_A1 DDR4_A2 DDR4_A3 DDR4_A4 DDR4_A5 DDR4_A6 DDR4_A7 DDR4_A8 DDR4_A9 DDR4_A10 DDR4_A11 DDR4_A12 DDR4_A13 DDR4_ACT_N DDR4_ALERT_N DDR4_BA0 DDR4_BA1 DDR4_BG0 DDR4_CAS DDR4_CKE0 DDR4_CS_B DDR4_DQS_ODT0 DDR4_PARITY DDR4_RAM_RST_N DDR4_RAS DDR4_TEN DDR4_WE
component class U_Power_48_20V@3A: C595 C596 C597 C598 C693 C694 C695 C696 C697 C698 C699 C700 C701 C702 C703 C704 D26 D27 L22 R140 R149 R150 R159 R160 R665 R666 R667 R669 R670 R764 T34 T35 U65
net class WR_CLK_C: WR_Source_CLK_N WR_Source_CLK_P
net class WR_CLK_C_LMK: WR_LMK_CLK_IN_N WR_LMK_CLK_IN_P
net class WR_CLK2: WR_LMK_CLK_HF2_N WR_LMK_CLK_HF2_P
net class WR_CLK1: WR_LMK_CLK_HF1_N WR_LMK_CLK_HF1_P
net class RAIL_CLK: CLK_Fanout_In_N CLK_Fanout_In_P
net class PCIE4_SysRef_FPGA: PCIE4_SysRef_FPGA_N PCIE4_SysRef_FPGA_P
net class PCIE3_SysRef_FPGA: PCIE3_SysRef_FPGA_N PCIE3_SysRef_FPGA_P
net class PCIE2_SysRef_FPGA: PCIE2_SysRef_FPGA_N PCIE2_SysRef_FPGA_P
net class PCIE1_SysRef_FPGA: PCIE1_SysRef_FPGA_N PCIE1_SysRef_FPGA_P
net class PCIE0_Sysref_FPGA: PCIE0_SysRef_FPGA_N PCIE0_SysRef_FPGA_P
component class U_Pomiar_pradu_napiecia_1: C309_U_Pomiar_pradu_napiecia_1 R448_U_Pomiar_pradu_napiecia_1 U64_U_Pomiar_pradu_napiecia_1
component class U_Pomiar_pradu_napiecia_2: C309_U_Pomiar_pradu_napiecia_2 R448_U_Pomiar_pradu_napiecia_2 U64_U_Pomiar_pradu_napiecia_2
component class U_Pomiar_pradu_napiecia_3: C309_U_Pomiar_pradu_napiecia_3 R448_U_Pomiar_pradu_napiecia_3 U64_U_Pomiar_pradu_napiecia_3
component class U_Pomiar_pradu_napiecia_4: C309_U_Pomiar_pradu_napiecia_4 R448_U_Pomiar_pradu_napiecia_4 U64_U_Pomiar_pradu_napiecia_4
net class LTC_6952_3_REF: LTC6952_3_REF_N LTC6952_3_REF_P
net class LTC_6952_3_REF_SMA: LTC6952_3_REF_SMA_N LTC6952_3_REF_SMA_P
net class LTC_6952_2_REF: LTC6952_2_REF_P
net class LTC_6952_2_REF_SMA: LTC6952_2_REF_SMA_N LTC6952_2_REF_SMA_P
net class LTC_6952_1_REF: LTC6952_1_REF_N LTC6952_1_REF_P
net class Bank505_MGTRREFx_: CLK_GTR_T1_N CLK_GTR_T1_P CLK_GTR_T2_N CLK_GTR_T2_P CLK_GTR_T3_N CLK_GTR_T3_P
component class DAC: C320 C321 C322 C323 R481 R608 R609 U30 X2 X3
net class Si53323_2_Q2_LVDS: Si53323_2_Q2_LVDS_N Si53323_2_Q2_LVDS_P
net class Si53323_1_Q2_LVDS: Si53323_1_Q2_LVDS_N Si53323_1_Q2_LVDS_P
component class SFP_Group+IMU: R469 R470 R471 R472 R473 R474 R475 R476 R477 R478 R479 R480
component class HighSpeed: R427 R449 R450 R451 R452 R453 R454 R538
component class CLK_MUX: C324 C325 C326 C327 C328 C329 C330 C333 C336 C337 C338 C339 C340 C341 C342 C343 C344 C724 C725 C726 C727 FB23 FB24 J26 R245 R246 R247 R248 R249 R250 R251 R252 R253 R254 R255 R256 R257 R258 R259 R260 R261 R262 R263 R264 R265 R291 R301 R384 R385 R386 R387 R482 R483 R484 R485 R486 R487 R488 R489 T36 U31 U32 U33
net class Si53323_2_Q2: Si53323_2_Q2_N Si53323_2_Q2_P
net class Si53323_2_Q1: Si53323_2_Q1_P
net class Si53323_2_CLK1: Si53323_2_CLK1_N Si53323_2_CLK1_P
net class Si53323_1_Q2: Si53323_1_Q2_N Si53323_1_Q2_P
net class Si53323_1_Q1: Si53323_1_Q1_N
net class RefClk_Si53323: RefClk_Si53323_P
net class MUX_DIV_OUT: OSC_Out_DIV_P
net class MUX_DIV_OUT_I: Osc_in_Si53323_2_P
net class CLM_M_OSC_IN_C: OSC_500Out
net class CLK_SMA_2: CLK_SMA2_N CLK_SMA2_P
net class CLK_SMA_1: CLK_SMA1_N CLK_SMA1_P
net class CLK_SMA_0: CLK_SMA0_N CLK_SMA0_P
net class CLK_SMA2_C: CLK_SMA2_C_N CLK_SMA2_C_P
net class CLK_SMA1_C: CLK_SMA1_C_N CLK_SMA1_C_P
net class CLK_SMA0_C: CLK_SMA0_C_N CLK_SMA0_C_P
net class CLK_M_OSC_In: CLK_M_OSC_In
differential pair class Diff_76_to_90_Ram_DQS: DDR4_DQS_0 DDR4_DQS_1 DDR4_DQS_2 DDR4_DQS_3 DDR4_DQS_4 DDR4_DQS_5 DDR4_DQS_6 DDR4_DQS_7 DDR4_DQS_8
net class Single_36_39_50_Adr: DDR4_A0 DDR4_A1 DDR4_A2 DDR4_A3 DDR4_A4 DDR4_A5 DDR4_A6 DDR4_A7 DDR4_A8 DDR4_A9 DDR4_A10 DDR4_A11 DDR4_A12 DDR4_A13 DDR4_ACT_N DDR4_ALERT_N DDR4_BA0 DDR4_BA1 DDR4_BG0 DDR4_CAS DDR4_CKE0 DDR4_CS_B DDR4_DQS_ODT0 DDR4_PARITY DDR4_RAM_RST_N DDR4_RAS DDR4_TEN DDR4_WE
net class Diff_76_86_90: DDR4_DQS_0_N DDR4_DQS_0_P DDR4_DQS_1_N DDR4_DQS_1_P DDR4_DQS_2_N DDR4_DQS_2_P DDR4_DQS_3_N DDR4_DQS_3_P DDR4_DQS_4_N DDR4_DQS_4_P DDR4_DQS_5_N DDR4_DQS_5_P DDR4_DQS_6_N DDR4_DQS_6_P DDR4_DQS_7_N DDR4_DQS_7_P DDR4_DQS_8_N DDR4_DQS_8_P
net class RAM_Clock_Signal: DDR4_CK_N DDR4_CK_P
component class U_Pomiar_pradu_napiecia_5: C309_U_Pomiar_pradu_napiecia_5 R448_U_Pomiar_pradu_napiecia_5 U64_U_Pomiar_pradu_napiecia_5
component class U_Pomiar_pradu_napiecia_6: C309_U_Pomiar_pradu_napiecia_6 R448_U_Pomiar_pradu_napiecia_6 U64_U_Pomiar_pradu_napiecia_6
component class U_Pomiar_pradu_napiecia_7: C309_U_Pomiar_pradu_napiecia_7 R448_U_Pomiar_pradu_napiecia_7 U64_U_Pomiar_pradu_napiecia_7
component class U_Pomiar_pradu_napiecia_8: C309_U_Pomiar_pradu_napiecia_8 R448_U_Pomiar_pradu_napiecia_8 U64_U_Pomiar_pradu_napiecia_8
component class U_Pomiar_pradu_napiecia_9: C309_U_Pomiar_pradu_napiecia_9 R448_U_Pomiar_pradu_napiecia_9 U64_U_Pomiar_pradu_napiecia_9
component class U_5V_to_3V31: C563_U_5V_to_3V31 C564_U_5V_to_3V31 C565_U_5V_to_3V31 C566_U_5V_to_3V31 C567_U_5V_to_3V31 R430_U_5V_to_3V31 R431_U_5V_to_3V31 R432_U_5V_to_3V31 U59_U_5V_to_3V31
channel class Pomiar_pradu_napiecia: U_Pomiar_pradu_napiecia_10 U_Pomiar_pradu_napiecia_11
net class Single_39_50_D: DDR4_DM0 DDR4_DM1 DDR4_DM2 DDR4_DM3 DDR4_DM4 DDR4_DM5 DDR4_DM6 DDR4_DM7 DDR4_DQ0 DDR4_DQ1 DDR4_DQ2 DDR4_DQ3 DDR4_DQ4 DDR4_DQ5 DDR4_DQ6 DDR4_DQ7 DDR4_DQ8 DDR4_DQ9 DDR4_DQ10 DDR4_DQ11 DDR4_DQ12 DDR4_DQ13 DDR4_DQ14 DDR4_DQ15 DDR4_DQ16 DDR4_DQ17 DDR4_DQ18 DDR4_DQ19 DDR4_DQ20 DDR4_DQ21 DDR4_DQ22 DDR4_DQ23 DDR4_DQ24 DDR4_DQ25 DDR4_DQ26 DDR4_DQ27 DDR4_DQ28 DDR4_DQ29 DDR4_DQ30 DDR4_DQ31 DDR4_DQ32 DDR4_DQ33 DDR4_DQ34 DDR4_DQ35 DDR4_DQ36 DDR4_DQ37 DDR4_DQ38 DDR4_DQ39 DDR4_DQ40 DDR4_DQ41 DDR4_DQ42 DDR4_DQ43 DDR4_DQ44 DDR4_DQ45 DDR4_DQ46 DDR4_DQ47 DDR4_DQ48 DDR4_DQ49 DDR4_DQ50 DDR4_DQ51 DDR4_DQ52 DDR4_DQ53 DDR4_DQ54 DDR4_DQ55 DDR4_DQ56 DDR4_DQ57 DDR4_DQ58 DDR4_DQ59 DDR4_DQ60 DDR4_DQ61 DDR4_DQ62 DDR4_DQ63
component class "Xilinx FPGA": R124 R363 R364 R365 R395 R398 R506 R507 R514 R515 R522 R523 R530 R531 R546 R547 R548 R549 R550 R551 R552 R553 R554 R555 R556 R557 R607 R618 R659 R660 R661 R662 R663 R664 R688 R735 R736 R744 R765 R766 R767 R817 R818 R819 R820 R821 R822 R823 R824 TP43 TP44 TP45 TP46 TP47 TP48 TP49 U15
component class U_Pomiar_pradu_napiecia_10: C309_U_Pomiar_pradu_napiecia_10 R448_U_Pomiar_pradu_napiecia_10 U64_U_Pomiar_pradu_napiecia_10
component class U_Pomiar_pradu_napiecia_11: C309_U_Pomiar_pradu_napiecia_11 R448_U_Pomiar_pradu_napiecia_11 U64_U_Pomiar_pradu_napiecia_11
component class PowerDistribition: P7 P8 P9 P10 P11 R229 R230 R455 R456 R457 R458 R459 R460 R461 R462 R463 R464 R465 R466 R467 R468 R593 R594 R595 R596 R597 R598 TP91 TP92
net class Single_50: CLK_Fanout_In_N CLK_Fanout_In_P CLK_GTR_T1_N CLK_GTR_T1_P CLK_GTR_T2_N CLK_GTR_T2_P CLK_GTR_T3_N CLK_GTR_T3_P CLK_Hi_Rail1_N CLK_Hi_Rail1_P CLK_Hi_Rail1_SysRef_P CLK_Hi_Rail2_N CLK_Hi_Rail2_P CLK_Hi_Rail2_SysRef_P CLK_M_OSC_In CLK_NVME_Conn_N CLK_NVME_Conn_P CLK_Q223_T1_N CLK_Q223_T1_P CLK_Q224_T1_N CLK_Q224_T1_P CLK_Q225_T1_N CLK_Q225_T1_P CLK_Q226_T1_N CLK_Q226_T1_P CLK_SMA0_C_N CLK_SMA0_C_P CLK_SMA0_N CLK_SMA0_P CLK_SMA1_C_N CLK_SMA1_C_P CLK_SMA1_N CLK_SMA1_P CLK_SMA2_C_N CLK_SMA2_C_P CLK_SMA2_N CLK_SMA2_P LTC6952_1_REF_N LTC6952_1_REF_P LTC6952_1_VCO_N LTC6952_1_VCO_P LTC6952_2_REF_P LTC6952_2_REF_SMA_N LTC6952_2_REF_SMA_P LTC6952_3_REF_N LTC6952_3_REF_P LTC6952_3_REF_SMA_N LTC6952_3_REF_SMA_P NetC334_1 NetC335_2 NetC341_1 NetC588_1 NetC588_2 NetR543_1 NVME_C_RX_1_P NVME_C_RX_O_N NVME_C_RX_O_P NVME_C_TX_1_N NVME_C_TX_1_P NVME_C_TX_O_N NVME_C_TX_O_P NVMe_Rx_0_N NVMe_Rx_0_P NVMe_Rx_1_N NVMe_Rx_1_P NVMe_Tx_0_N NVMe_Tx_0_P NVMe_Tx_1_N NVMe_Tx_1_P OSC_500Out Osc_in_Si53323_2_P OSC_Out_DIV_N OSC_Out_DIV_P PCIE0_SysRef_FPGA_N PCIE0_SysRef_FPGA_P PCIE1_SysRef_FPGA_N PCIE1_SysRef_FPGA_P PCIE2_SysRef_FPGA_N PCIE2_SysRef_FPGA_P PCIE3_SysRef_FPGA_N PCIE3_SysRef_FPGA_P PCIE4_SysRef_FPGA_N PCIE4_SysRef_FPGA_P RefClk_Si53323_P SGMI_C_Rx_N SGMI_C_Rx_P SGMI_C_Tx_N SGMI_C_Tx_P SGMI_Rx_N SGMI_Rx_P SGMI_Tx_N SGMI_Tx_P Si53323_1_Q1_N Si53323_1_Q2_LVDS_N Si53323_1_Q2_LVDS_P Si53323_1_Q2_N Si53323_1_Q2_P Si53323_2_CLK1_N Si53323_2_CLK1_P Si53323_2_Q1_P Si53323_2_Q2_LVDS_N Si53323_2_Q2_LVDS_P Si53323_2_Q2_N Si53323_2_Q2_P TD_A_N TD_A_P TD_B_N TD_B_P TD_C_N TD_C_P TD_D_N TD_D_P WR_LMK_CLK_HF1_N WR_LMK_CLK_HF1_P WR_LMK_CLK_HF2_N WR_LMK_CLK_HF2_P WR_LMK_CLK_IN_N WR_LMK_CLK_IN_P WR_Source_CLK_N WR_Source_CLK_P XO_LMK05028_P
net class Singe_50: Bank505_MGTRREF0_C_N Bank505_MGTRREF0_C_P Bank505_MGTRREF2_C_N Bank505_MGTRREF2_C_P Bank505_MGTRREF3_C_N Bank505_MGTRREF3_C_P NetU2_L25 NetU2_L26
net class Bank505_MGTRREFx_C: Bank505_MGTRREF0_C_N Bank505_MGTRREF0_C_P Bank505_MGTRREF2_C_N Bank505_MGTRREF2_C_P Bank505_MGTRREF3_C_N Bank505_MGTRREF3_C_P NetU2_L25 NetU2_L26
net class Bank226_MGTREFx_to_C: CLK_Q226_T1_N CLK_Q226_T1_P
net class Bank225_MGTREFx_to_C: CLK_Q225_T1_N CLK_Q225_T1_P
net class Bank225_MGTREFx_C: Bank225_MGTREF0_C_N Bank225_MGTREF0_C_P Bank225_MGTREF1_C_N Bank225_MGTREF1_C_P
net class Bank224_MGTREFx_to_C: CLK_Q224_T1_N CLK_Q224_T1_P
net class Bank224_MGTREFx_C: Bank224_MGTREF0_C_N Bank224_MGTREF0_C_P Bank224_MGTREF1_C_N Bank224_MGTREF1_C_P
net class Bank223_MGTREFx_to_C: CLK_Q223_T1_N CLK_Q223_T1_P
net class Bank223_MGTREFx_C: Bank223_MGTREF0_C_N Bank223_MGTREF0_C_P Bank223_MGTREF1_C_N Bank223_MGTREF1_C_P
component class U_Translator_I2C4: TP60_U_Translator_I2C4 TP61_U_Translator_I2C4 U36_U_Translator_I2C4
net class SYNC: SYNC_PCIE0_N SYNC_PCIE0_P SYNC_PCIE1_N SYNC_PCIE1_P SYNC_PCIE2_N SYNC_PCIE2_P SYNC_PCIE3_N SYNC_PCIE3_P SYNC_PCIE4_N SYNC_PCIE4_P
